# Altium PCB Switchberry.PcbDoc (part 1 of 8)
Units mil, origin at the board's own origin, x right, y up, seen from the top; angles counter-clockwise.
Board outline 4500 x 3824.8 mil, 6 copper layers (L01-TOP, L02-GND, L03-SIG, L04-SIG, L05-GND, L06-BOT), stack 49.214 mil thick; 431 components, 322 nets, 1699 pads, 1274 vias.
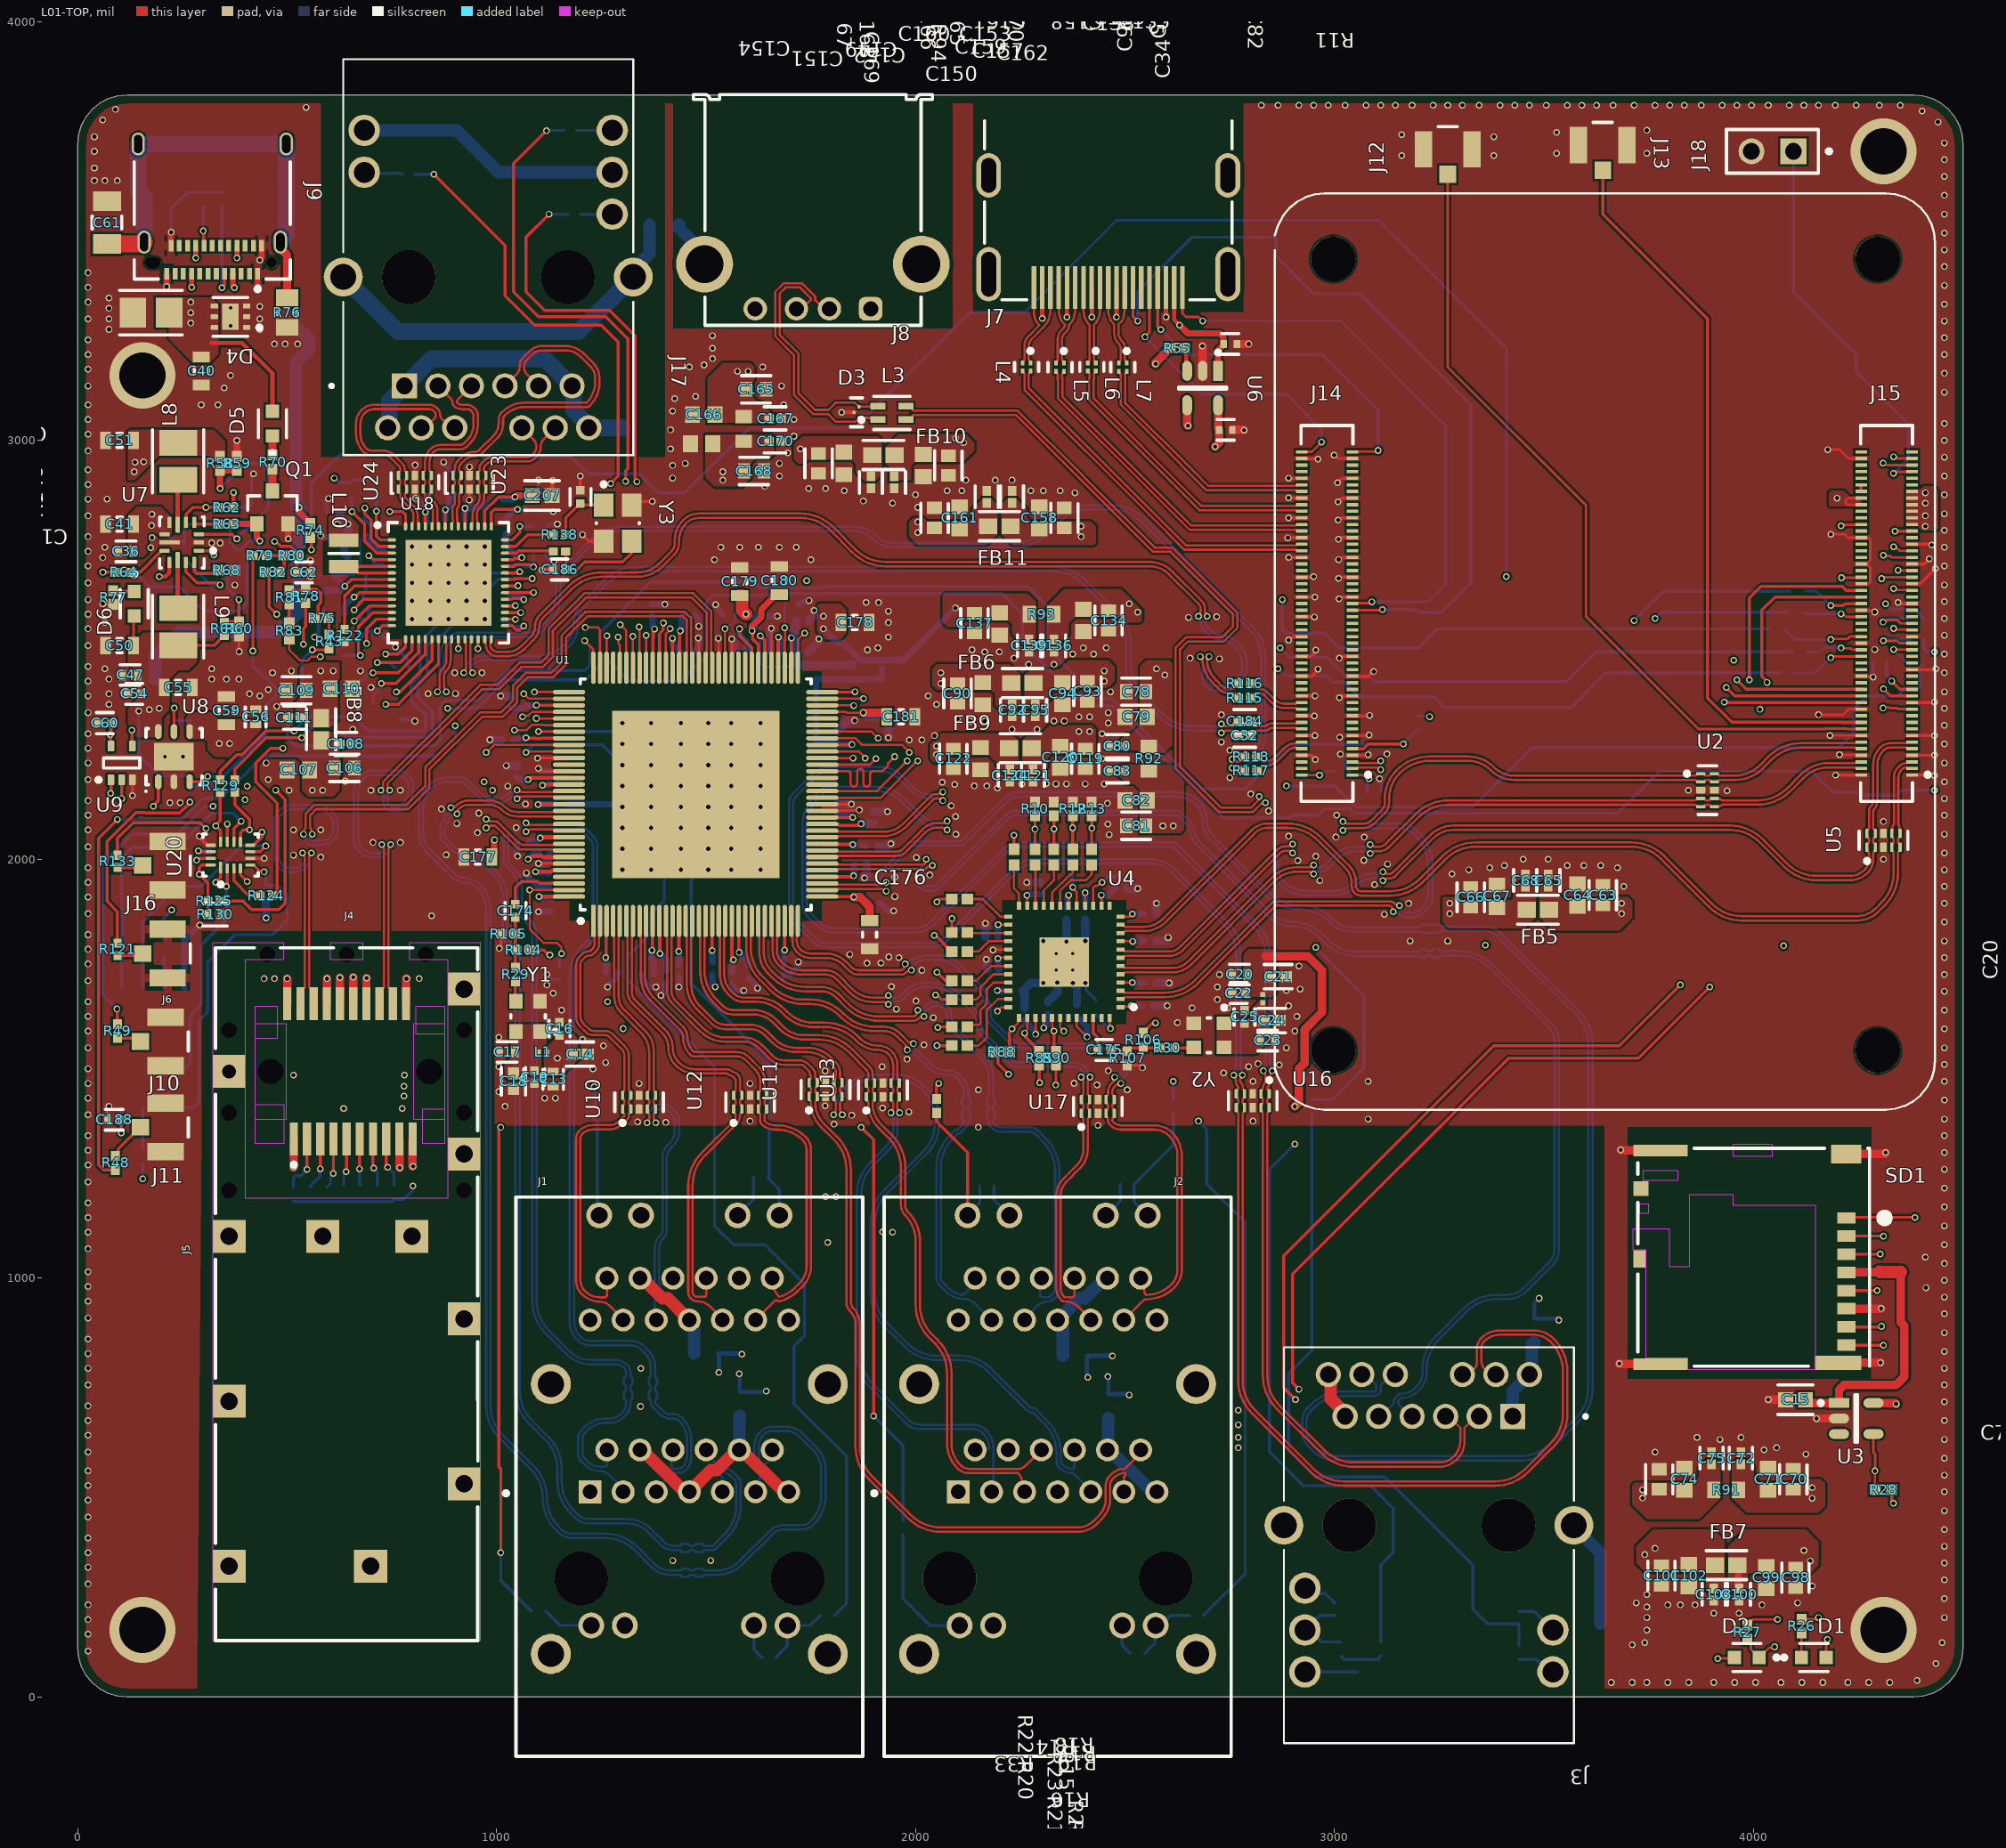
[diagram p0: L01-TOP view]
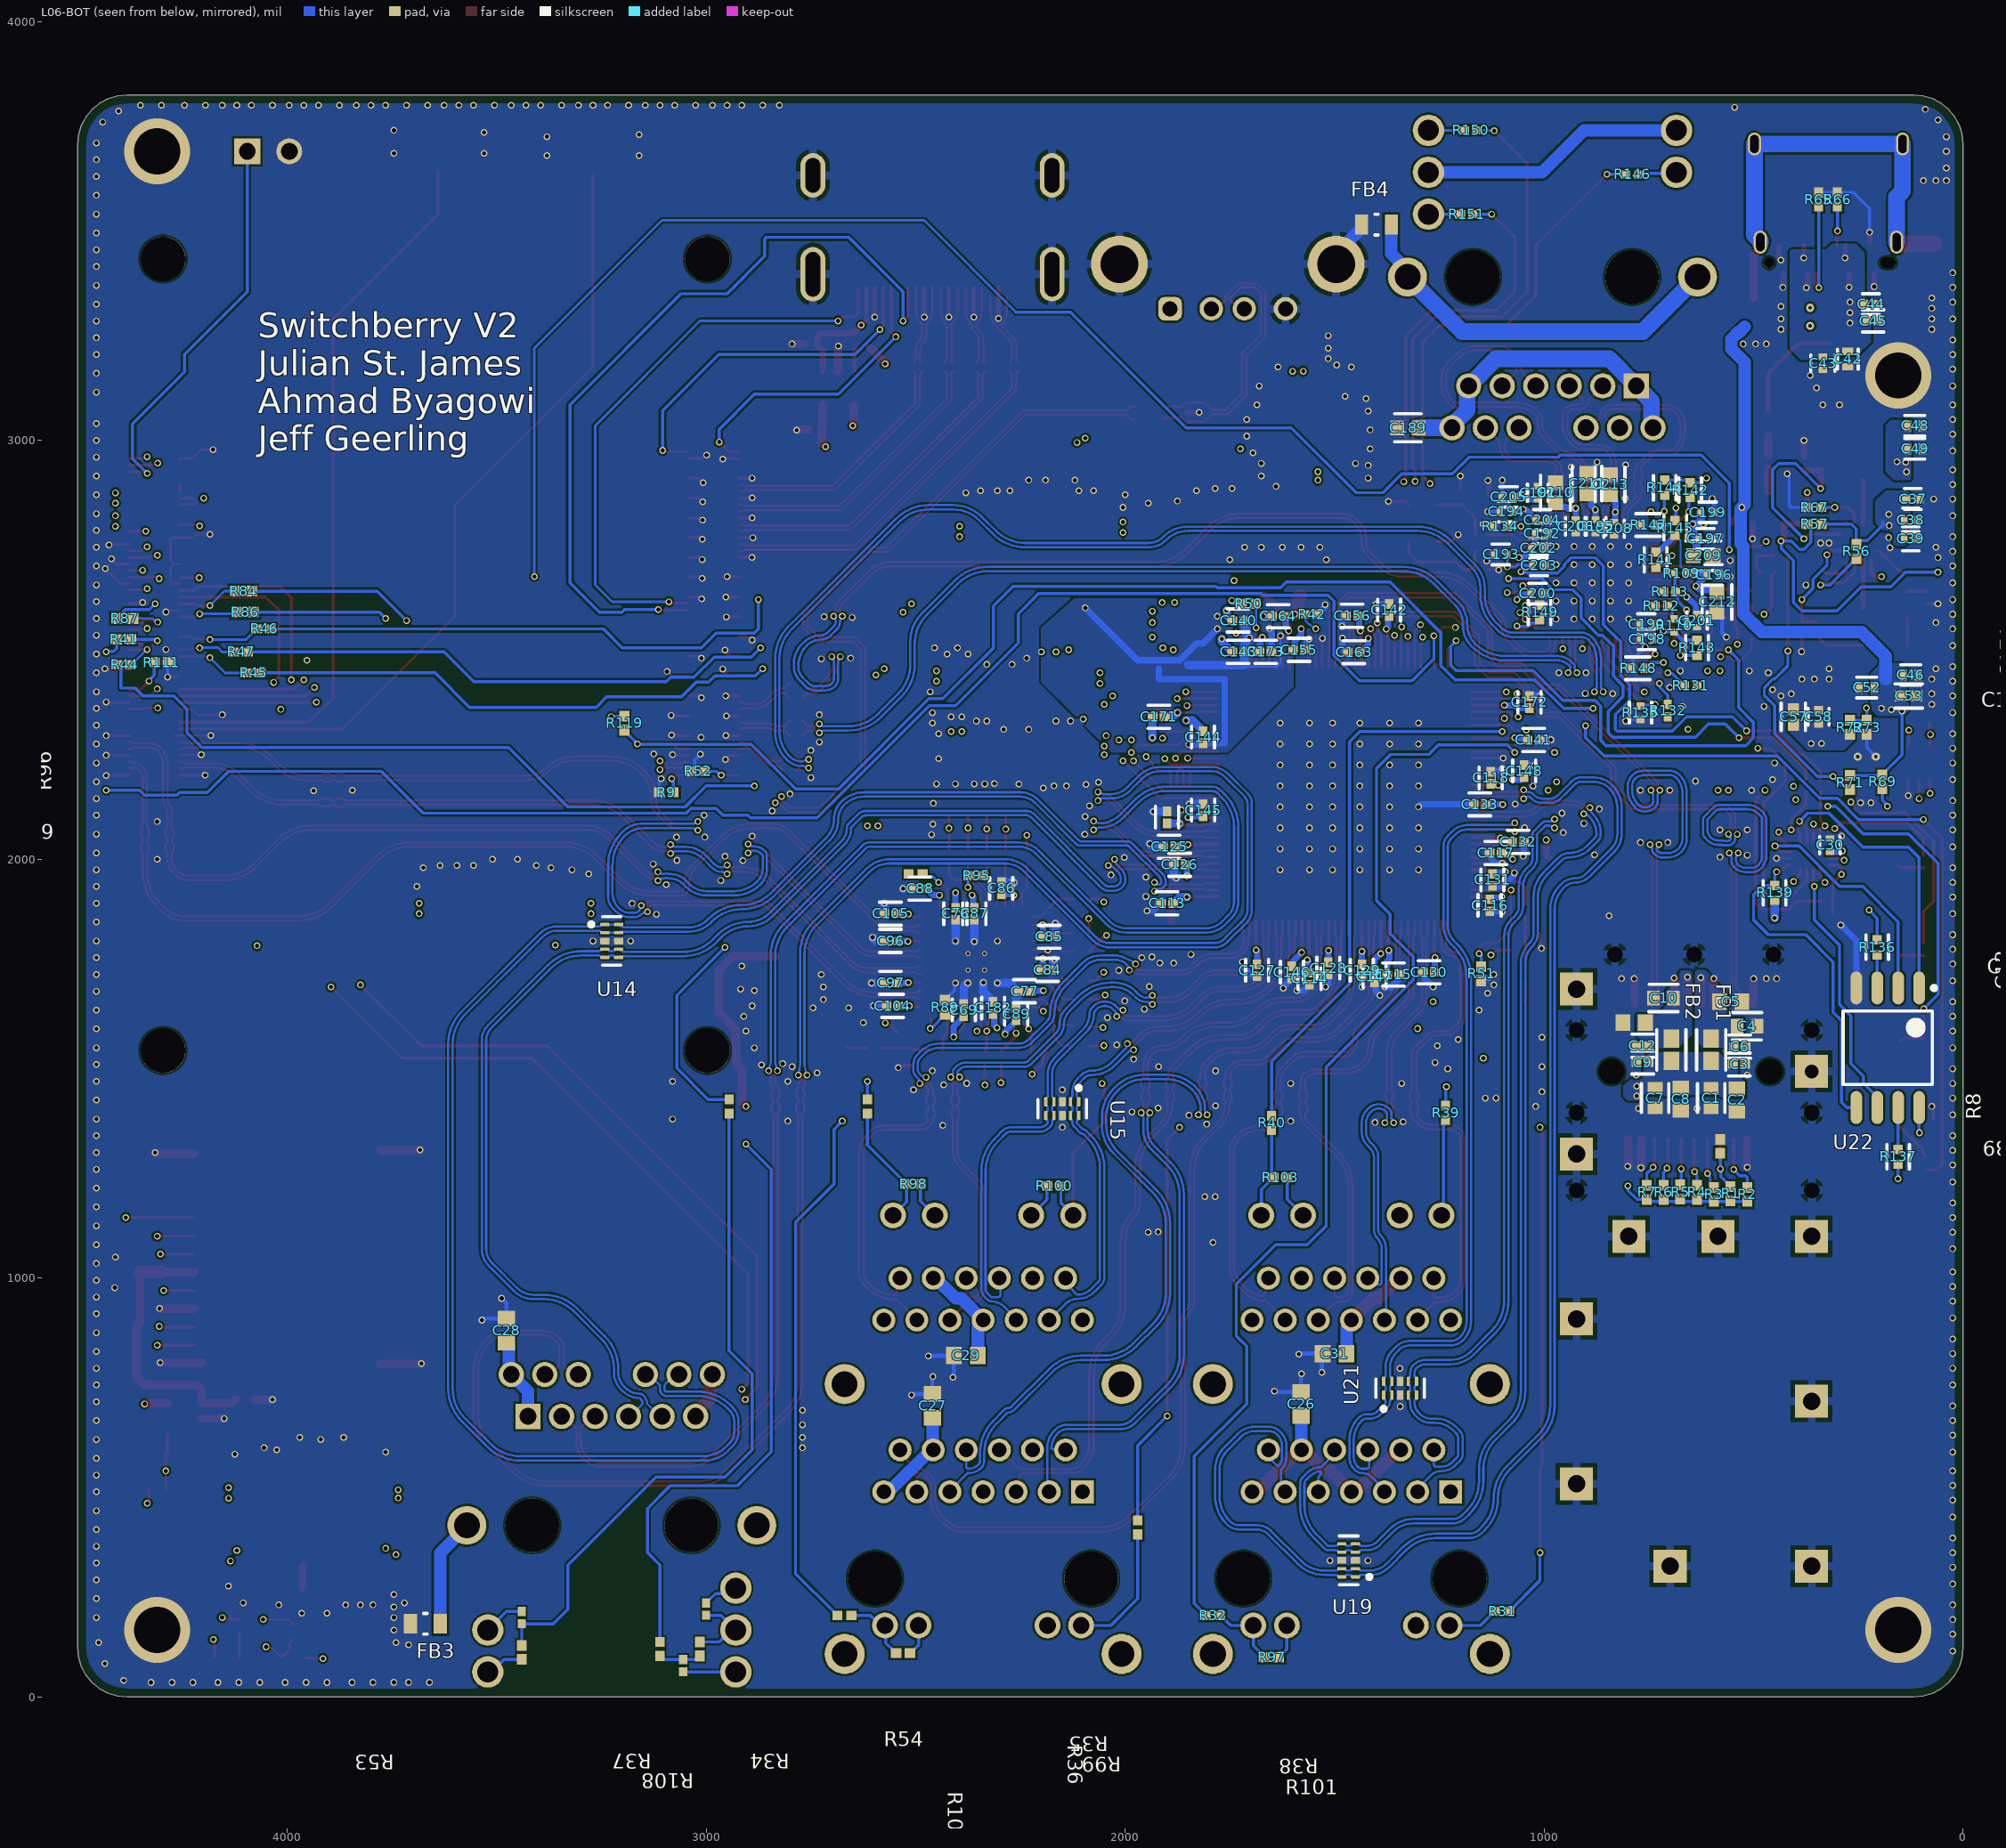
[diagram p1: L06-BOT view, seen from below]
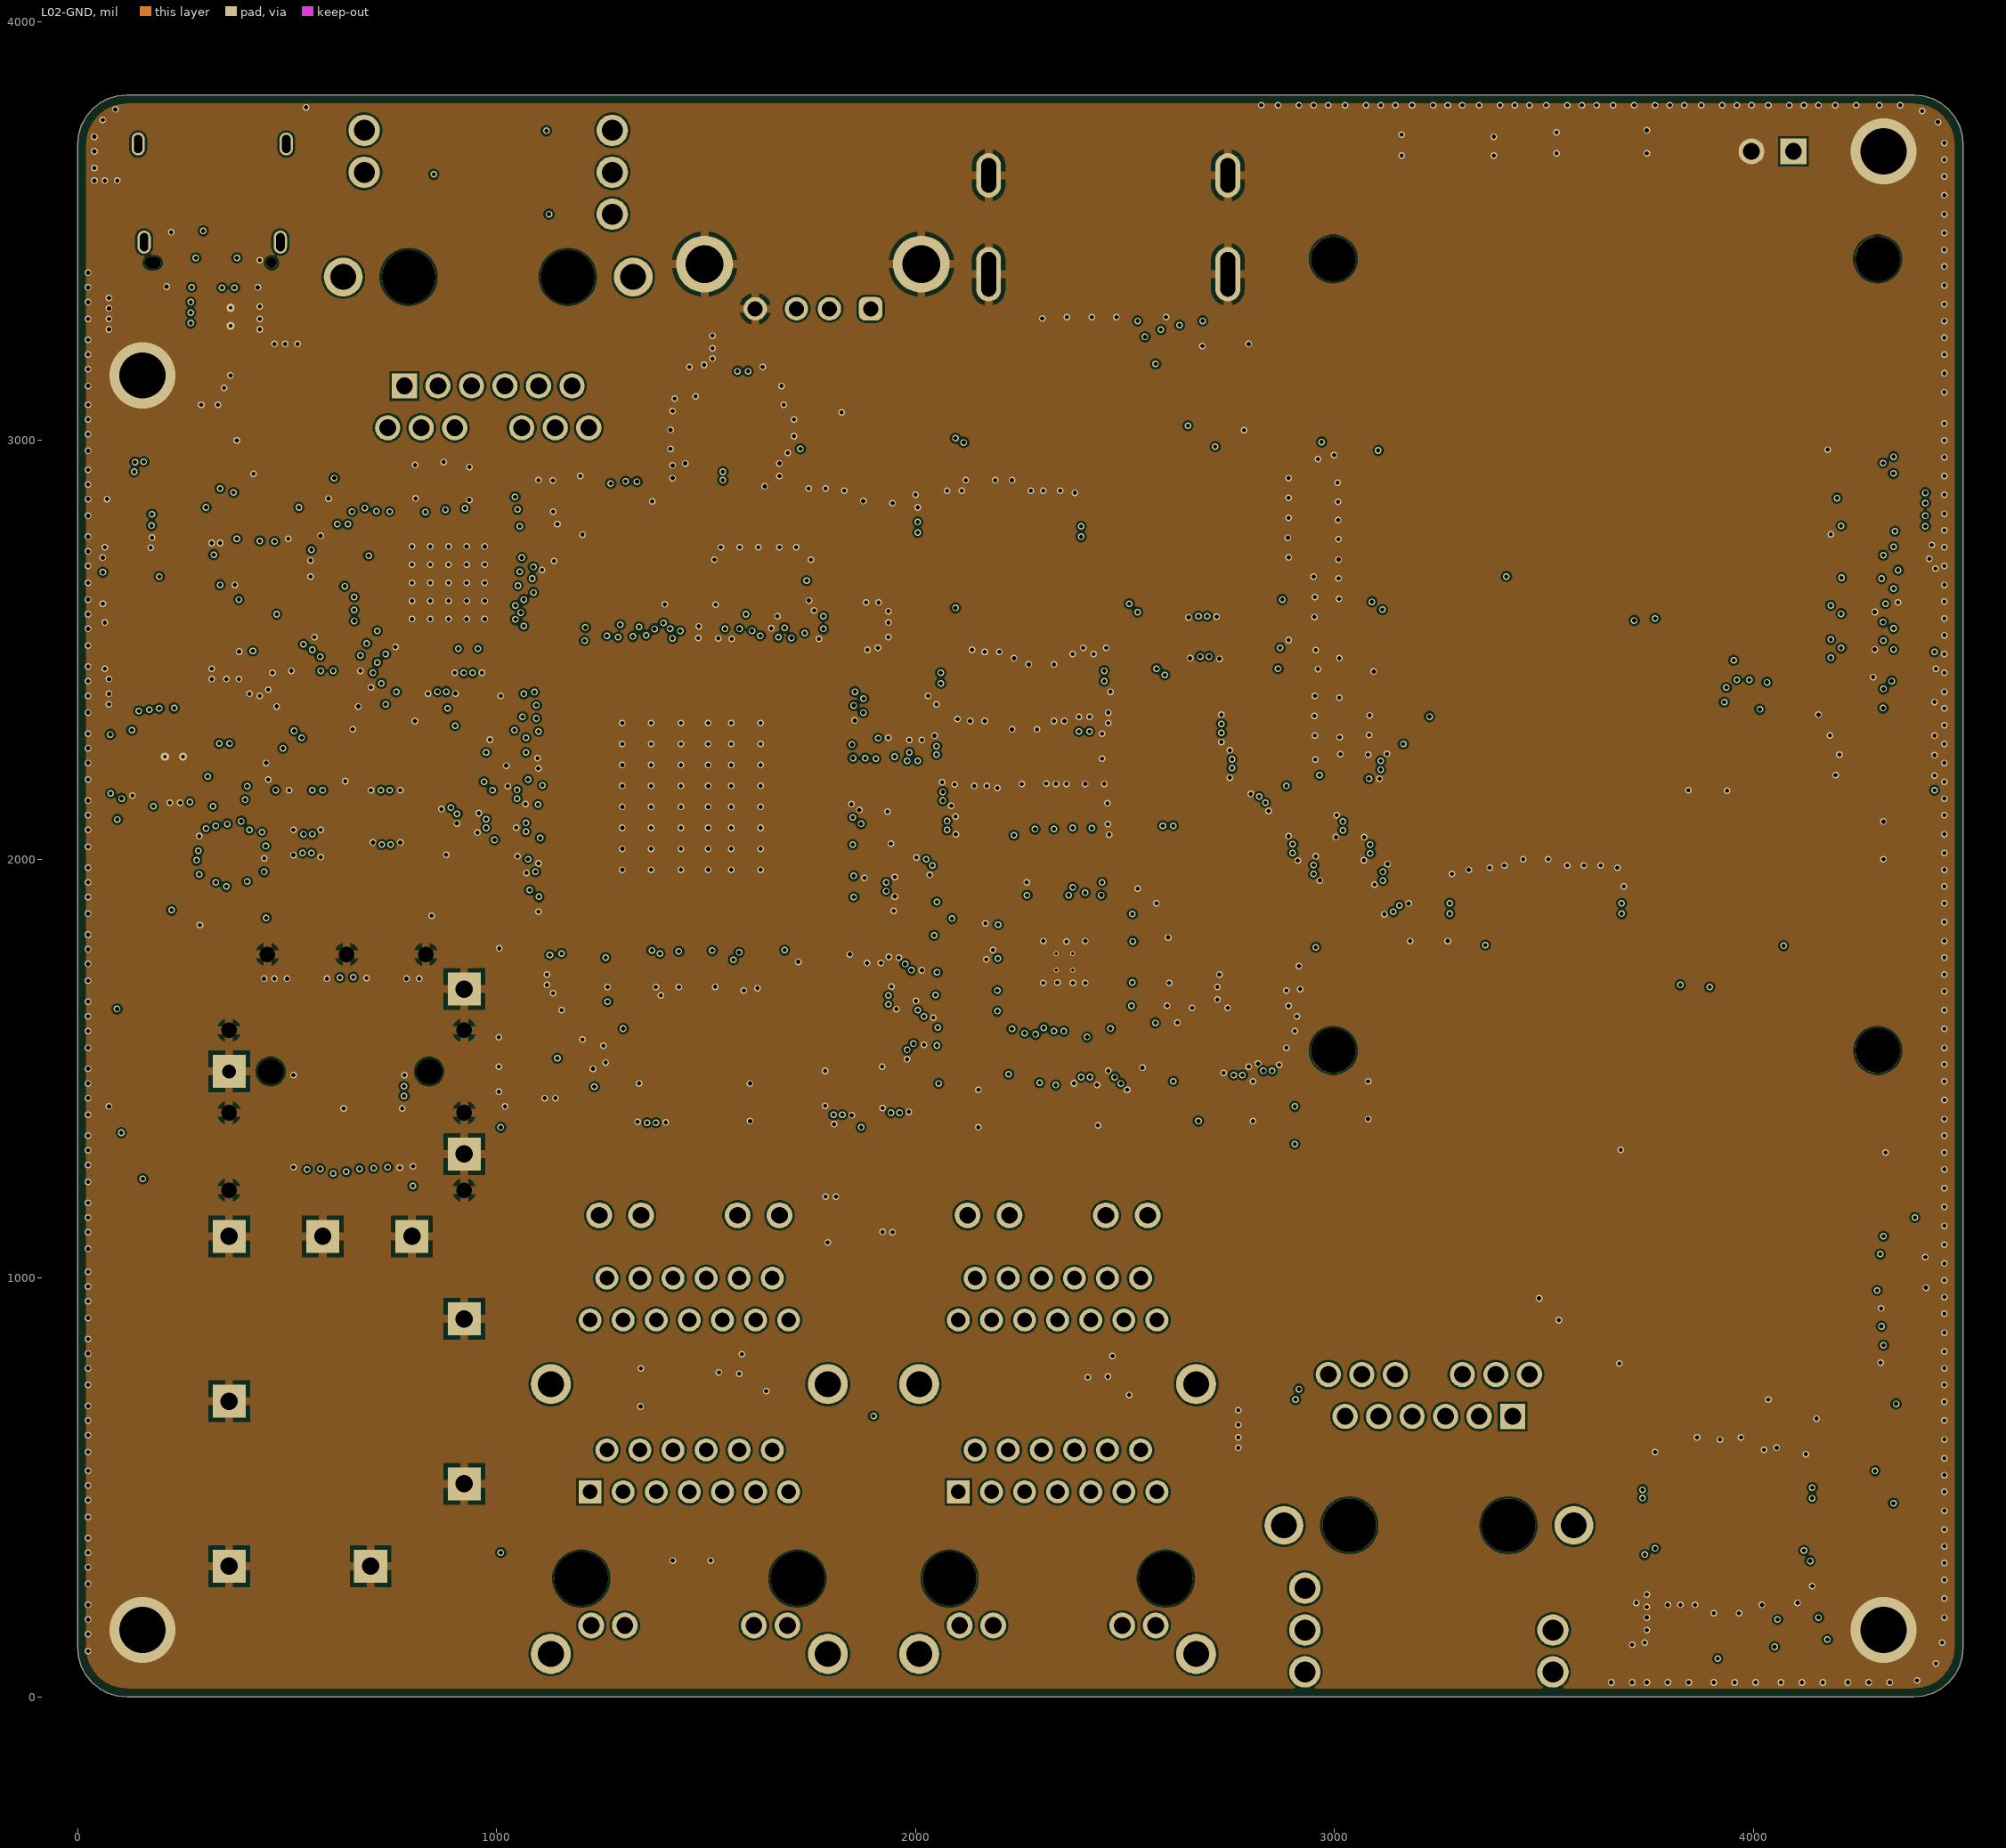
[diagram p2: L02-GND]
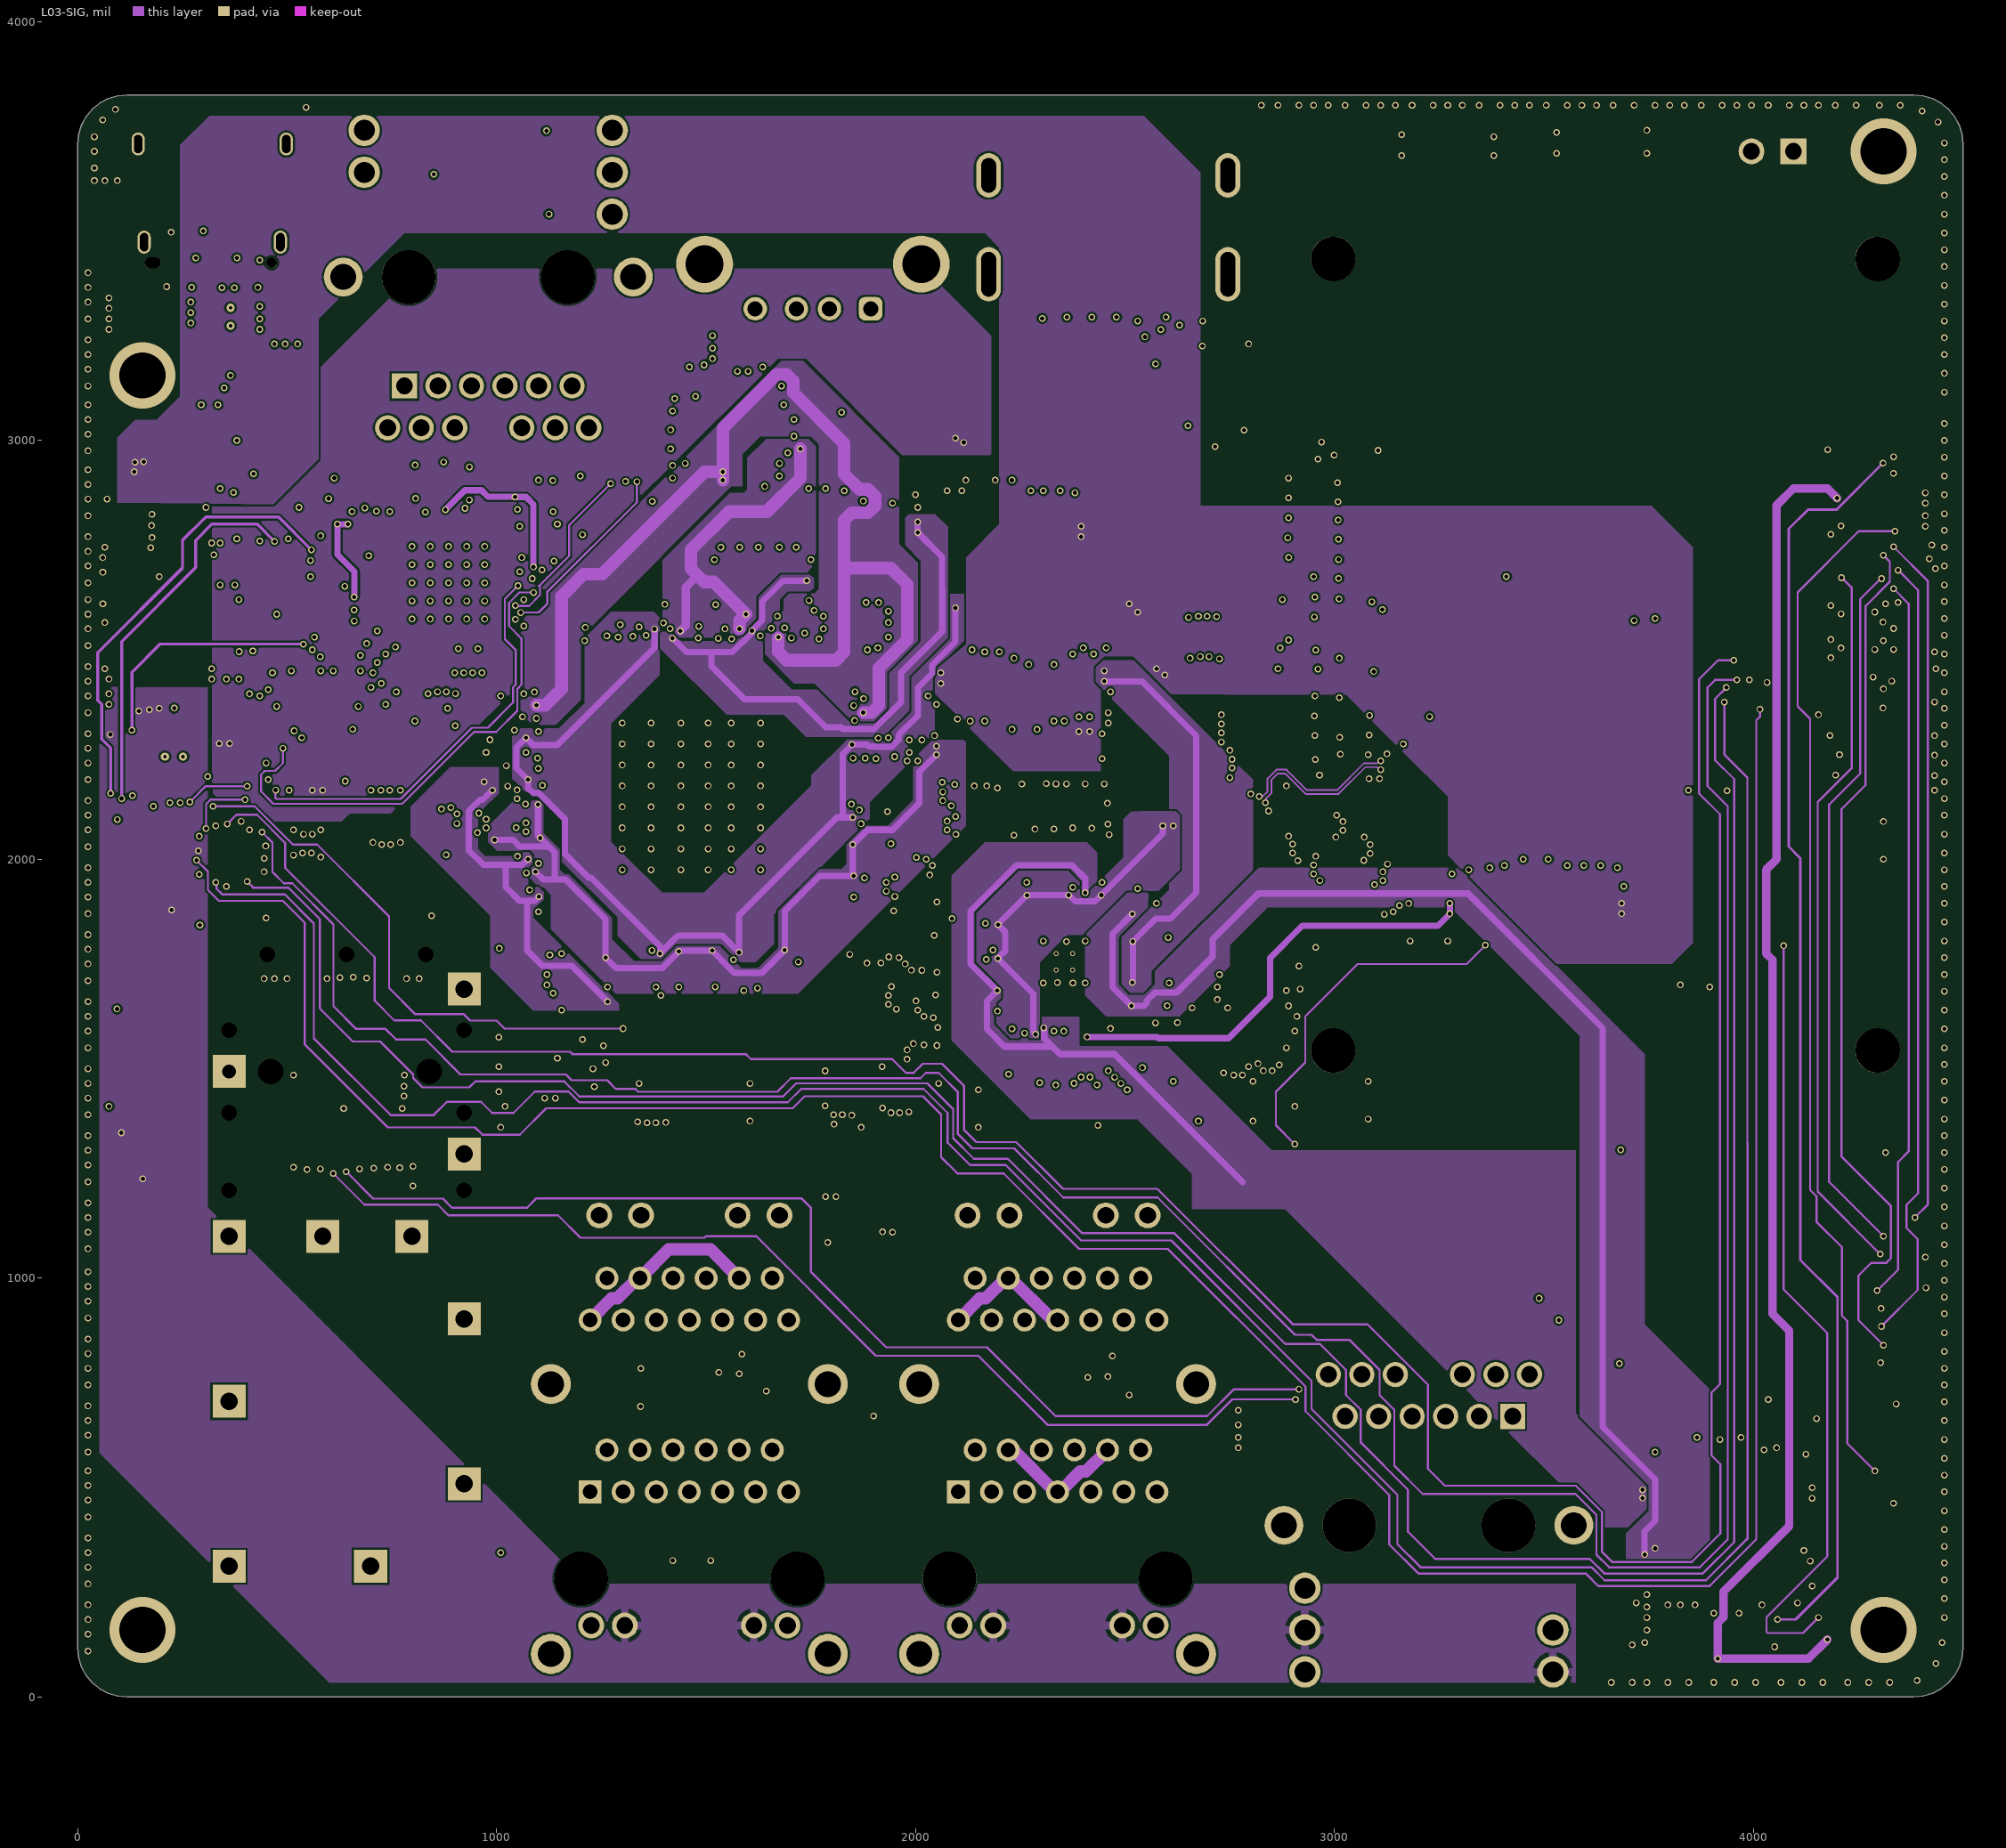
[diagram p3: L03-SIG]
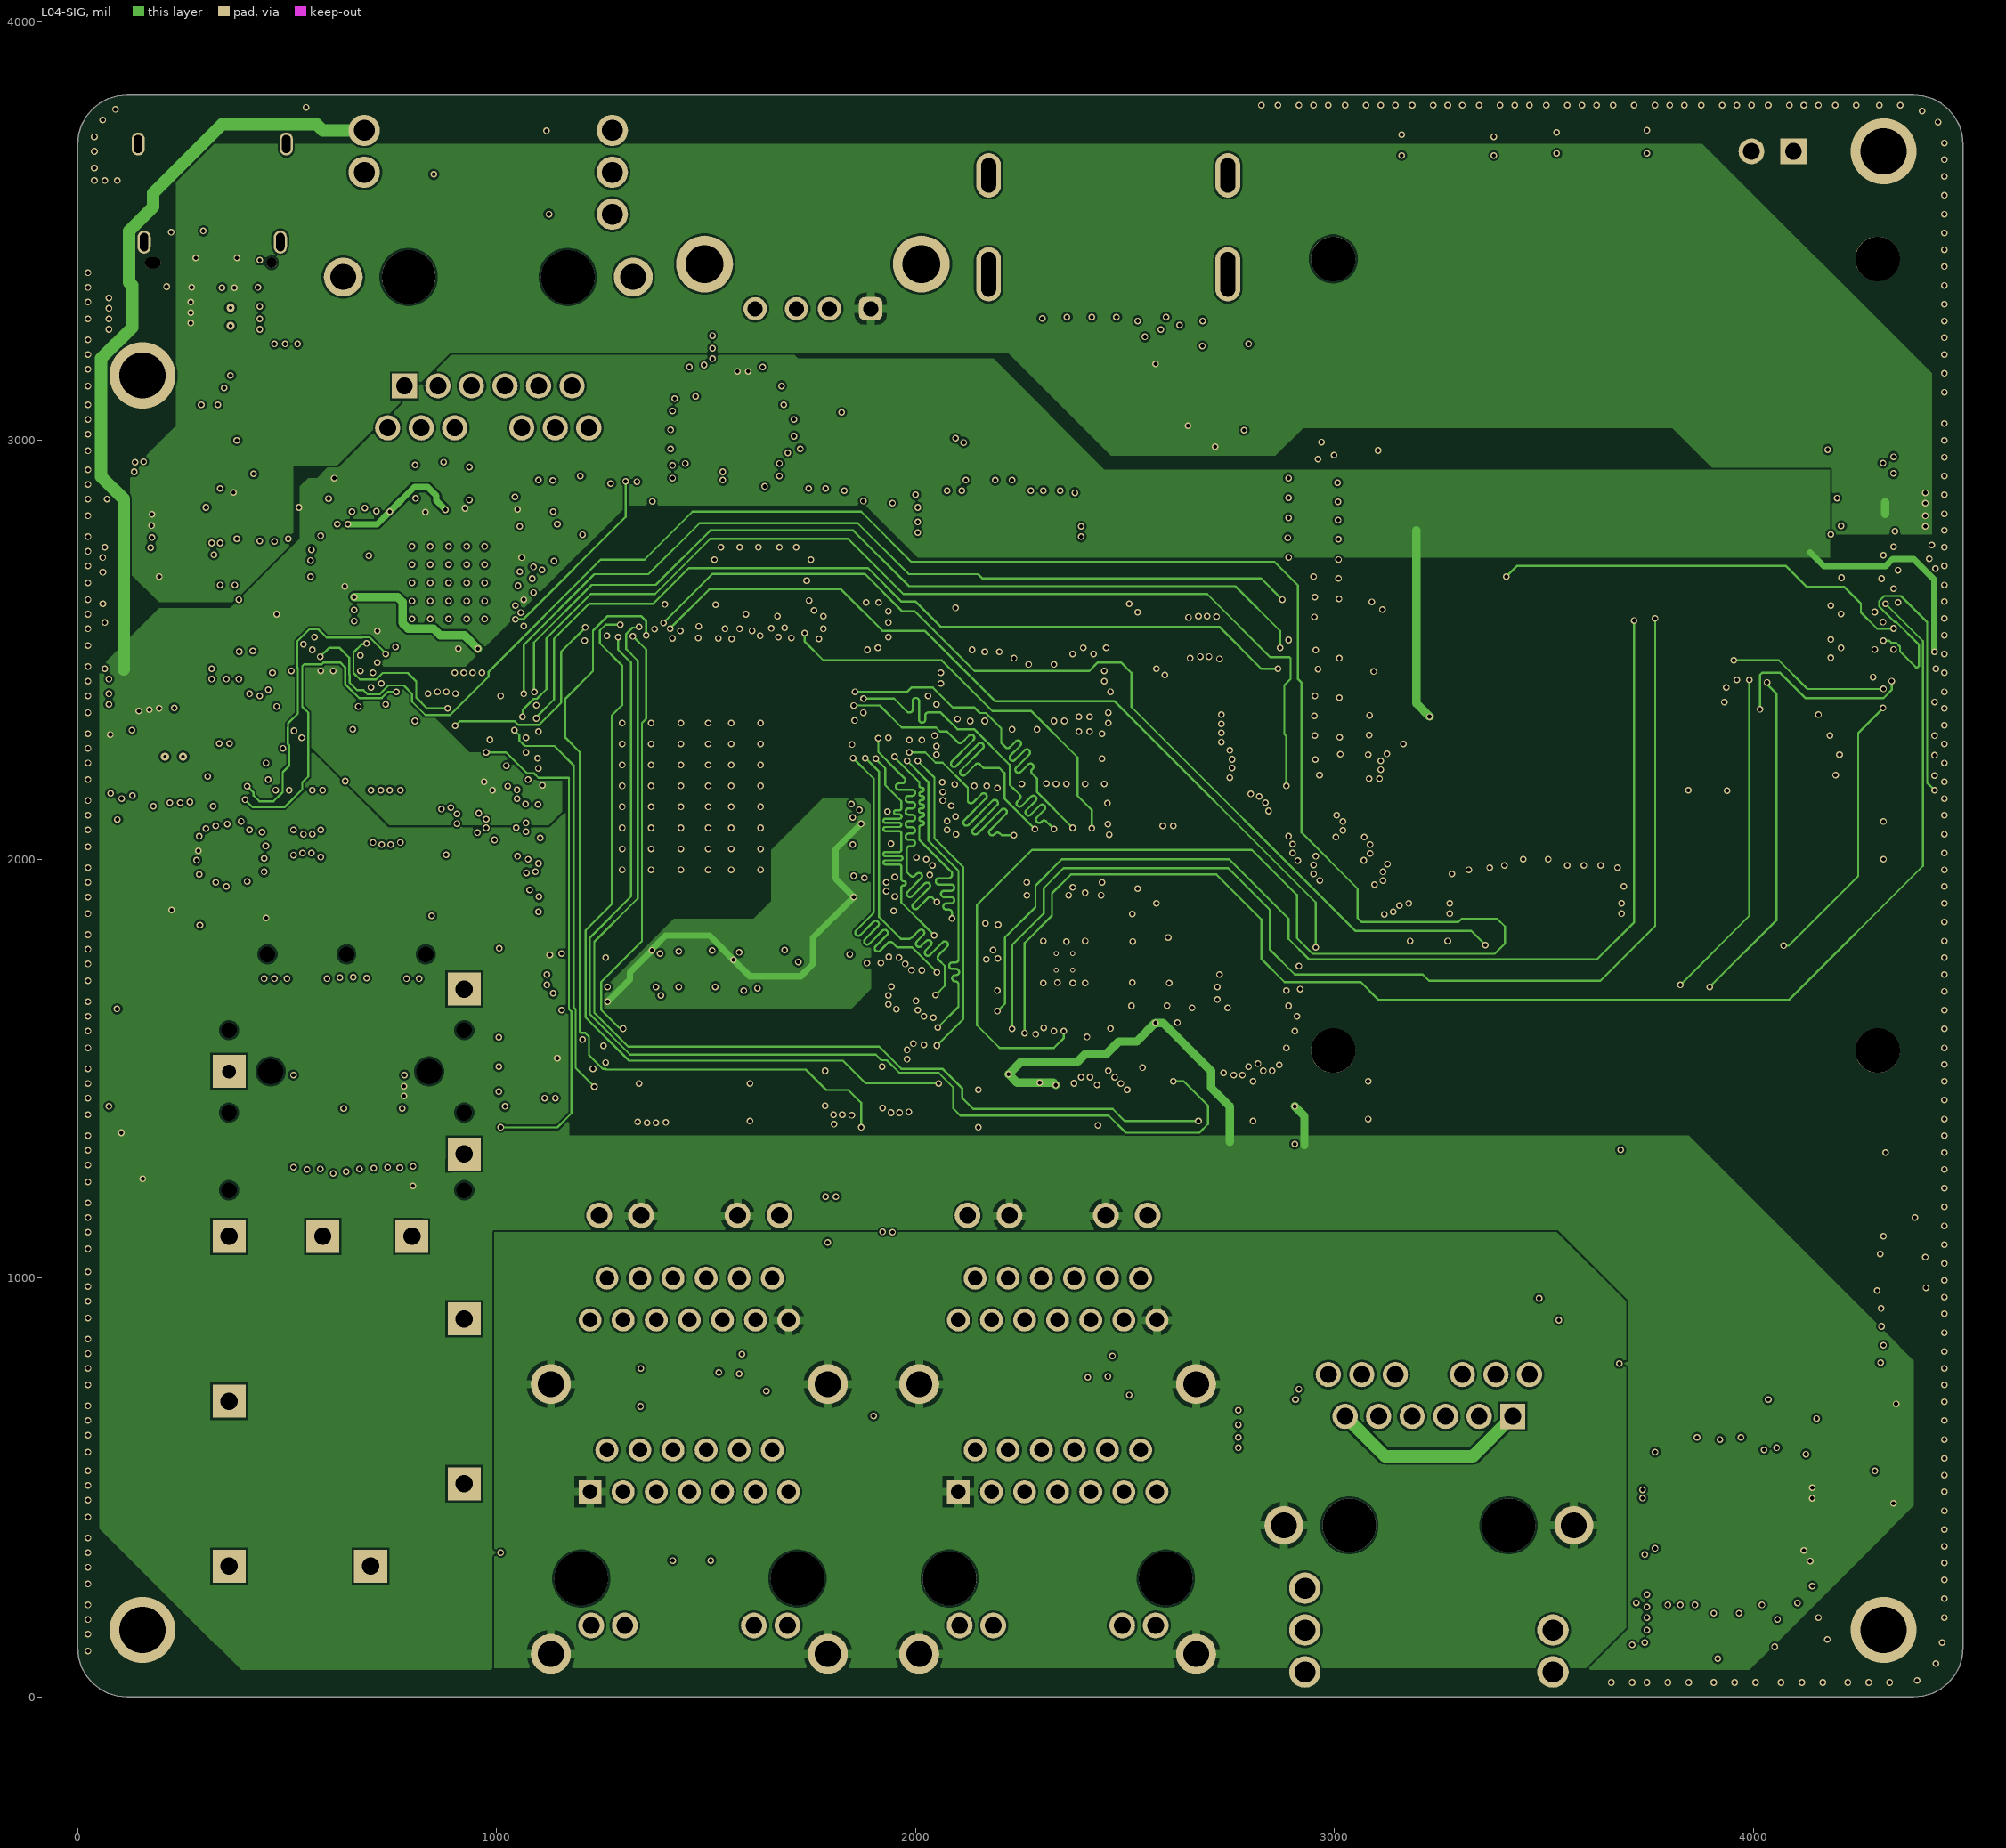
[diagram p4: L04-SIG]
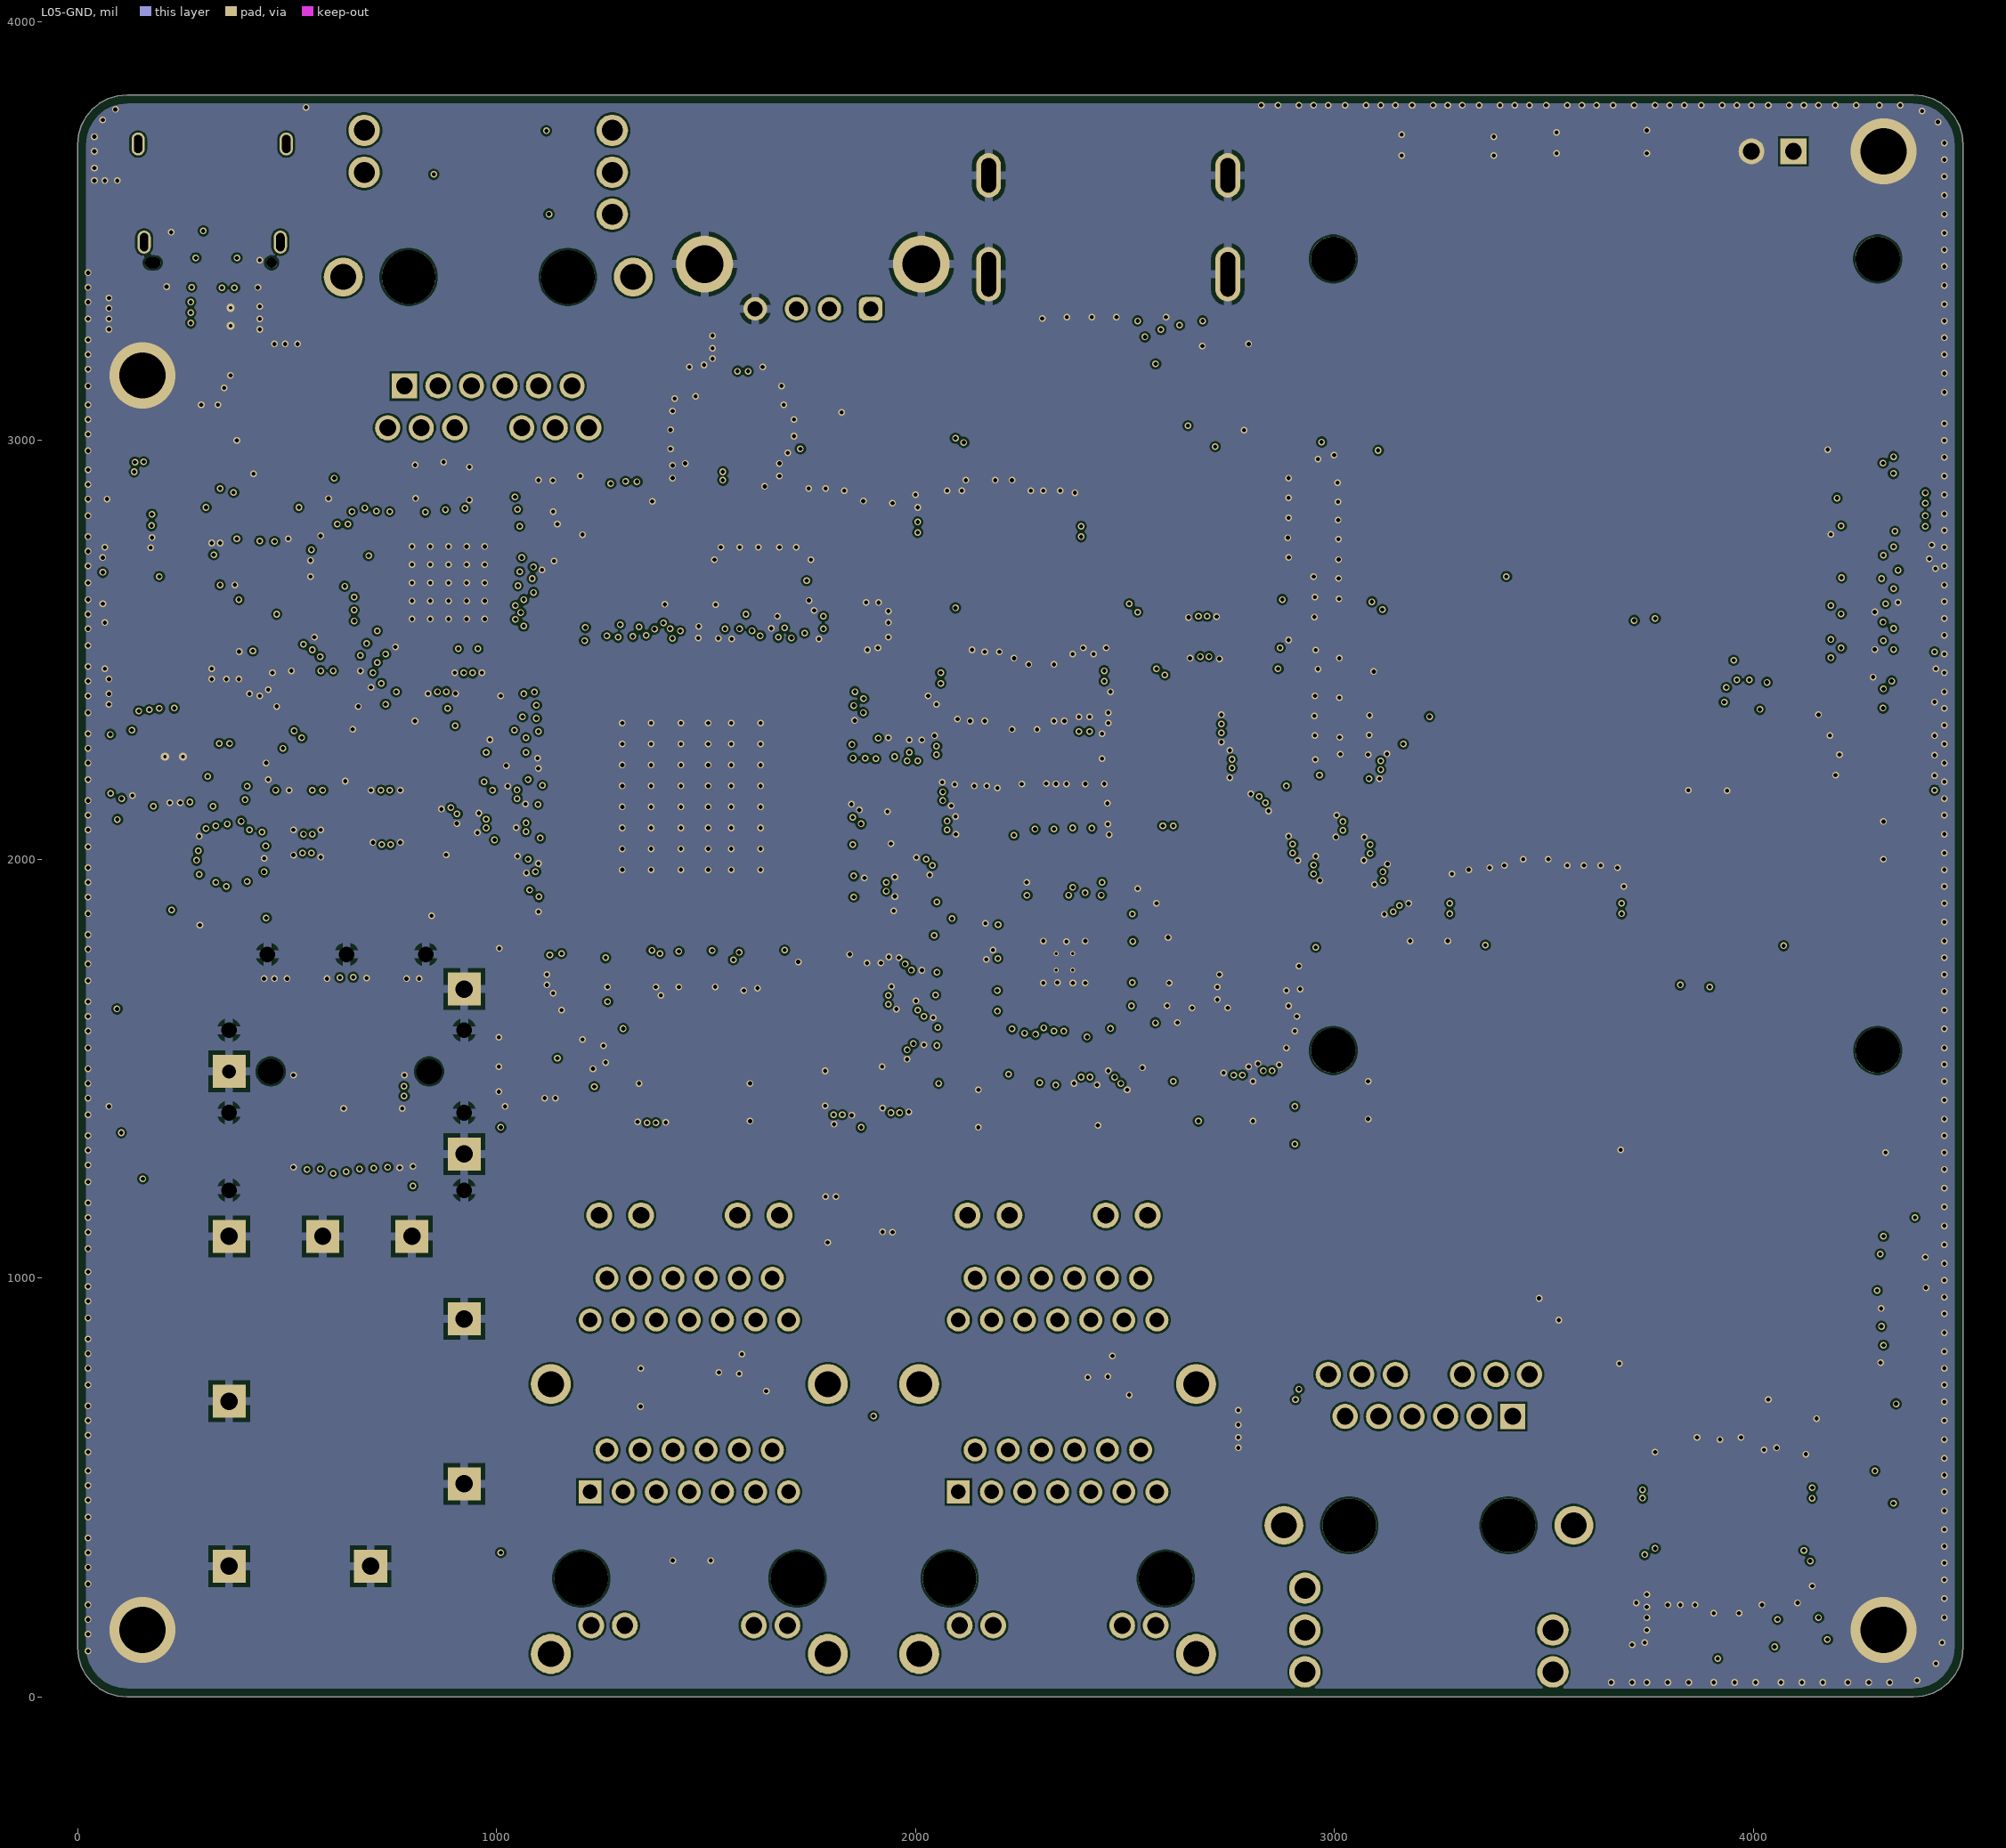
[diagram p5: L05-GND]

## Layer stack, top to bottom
Top Solder: solder mask 1, SM-001, Dk 4
L01-TOP: signal copper 1.378
Dielectric 1: prepreg 4.331, PP-017, Dk 4.3
L02-GND: signal copper 1.378
Dielectric 2: prepreg 4.331, PP-006, Dk 4.1
L03-SIG: signal copper 1.378
Dielectric 3: core 23.622, Core-039, Dk 4.8
L04-SIG: signal copper 1.378
Dielectric 4: prepreg 4.331, PP-006, Dk 4.1
L05-GND: signal copper 1.378
Dielectric 5: prepreg 4.331, PP-017, Dk 4.3
L06-BOT: signal copper 1.378
Bottom Solder: solder mask 1, SM-001, Dk 4

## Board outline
19.9,52.49 8.99,72.91 2.27,95.07 0,118.11 0,3706.69 2.27,3729.73 8.99,3751.89 19.9,3772.31 34.59,3790.21 52.49,3804.9 72.91,3815.81 95.07,3822.53 118.11,3824.8 4381.89,3824.8 4404.93,3822.53 4427.09,3815.81 4447.51,3804.9 4465.41,3790.21 4480.09,3772.31 4491.01,3751.89 4497.73,3729.73 4500,3706.69 4500,118.11 4497.73,95.07 4491.01,72.91 4480.09,52.49 4465.41,34.59 4447.51,19.9 4427.09,8.99 4404.93,2.27 4381.89,0 118.11,0 95.07,2.27 72.91,8.99 52.49,19.9 34.59,34.59

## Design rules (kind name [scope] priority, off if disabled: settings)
BoardOutlineClearance BoardOutlineClearance_Polygon [IsPolygon] p1: gap=20 ignorepadtopadclearanceinfootprint=FALSE
Clearance [All] p1: gap=5 ignorepadtopadclearanceinfootprint=FALSE
DiffPairsRouting [InDifferentialPairClass('All Differential Pairs')] p1: maxlimit=10 minlimit=5 mostfreqgap=5 toplayer_maxgap=5 toplayer_minwidth=5.38 toplayer_maxwidth=5.38 toplayer_prefwidth=5.38 midlayer1_maxgap=5 midlayer1_minwidth=4.04 midlayer1_maxwidth=4.04 midlayer1_prefwidth=4.04 midlayer2_maxgap=5 midlayer2_minwidth=4.04 midlayer2_maxwidth=4.04 midlayer2_prefwidth=4.04 bottomlayer_maxgap=5 bottomlayer_minwidth=5.38 bottomlayer_maxwidth=5.38 bottomlayer_prefwidth=5.38 impedanceprofiledriven=TRUE impedanceprofileid={2709FB12-8ABA-42C7-AB7C-5644AE441E76} impedanceprofilevalue=100.000000 maxuncoupledlength=500
HoleSize [All] p1: absolutevalues=TRUE maxlimit=120 minlimit=6 maxpercent=80.000 minpercent=20.000
PlaneClearance [All] p1: clearance=8
PlaneConnect [All] p1: planeconnectstyle=Direct reliefexpansion=20 reliefentries=4 reliefconductorwidth=10 reliefairgap=10
PolygonConnect ConnectorThermalRelief_Connect [All vs InComponent('J1') OR InComponent('J5') OR InComponent('J4') OR InComponent('J2') OR InComponent('J3') OR InComponent('SD1') OR InComponent('CM4') OR InComponent('J7') OR InComponent('J8') OR InComponent('J6') OR InComponent('J9')] p1: connectstyle=Relief reliefconductorwidth=20 reliefentries=4 polygonreliefangle="90 Angle" airgapwidth=10
PolygonConnect [All] p2: connectstyle=Direct reliefconductorwidth=10 reliefentries=4 polygonreliefangle="90 Angle" airgapwidth=10
RoutingVias [All] p1: holewidth=10 width=16 viastyle="Through Hole" minholewidth=6 minwidth=10 maxholewidth=50 maxwidth=100
SolderMaskExpansion [All] p1: expansion=4 istentingtop=FALSE
SupplyNets "Schematic Supply Nets_4" [InNet('P0V95_I225')] p1: voltage=0.000
SupplyNets "Schematic Supply Nets_24" [InNet('SW_AVDDL')] p2: voltage=0.000
SupplyNets "Schematic Supply Nets_23" [InNet('SW_VDDHS')] p3: voltage=0.000
SupplyNets "Schematic Supply Nets_22" [InNet('SW_DVDDL')] p4: voltage=0.000
SupplyNets "Schematic Supply Nets_21" [InNet('SW_VDDIO')] p5: voltage=0.000
SupplyNets "Schematic Supply Nets_20" [InNet('CHASSIS_GND')] p6: voltage=0.000
SupplyNets "Schematic Supply Nets_19" [InNet('SW_AVDDH')] p7: voltage=0.000
SupplyNets "Schematic Supply Nets_18" [InNet('CHASSIS_CM4_GND')] p8: voltage=0.000
SupplyNets "Schematic Supply Nets_17" [InNet('P2V5')] p9: voltage=0.000
SupplyNets "Schematic Supply Nets_16" [InNet('SW_VDDLS')] p10: voltage=0.000
SupplyNets "Schematic Supply Nets_15" [InNet('PHY_AVDDL')] p11: voltage=0.000
SupplyNets "Schematic Supply Nets_14" [InNet('P1V2')] p12: voltage=0.000
SupplyNets "Schematic Supply Nets_13" [InNet('PHY_AVDDL_PLL')] p13: voltage=0.000
SupplyNets "Schematic Supply Nets_12" [InNet('PHY_AVDDH')] p14: voltage=0.000
SupplyNets "Schematic Supply Nets_11" [InNet('PHY_DVDDL')] p15: voltage=0.000
SupplyNets "Schematic Supply Nets_10" [InNet('PHY_DVDDH')] p16: voltage=0.000
SupplyNets "Schematic Supply Nets_9" [InNet('P3V3_CM4')] p17: voltage=0.000
SupplyNets "Schematic Supply Nets_8" [InNet('P5V')] p18: voltage=0.000
SupplyNets "Schematic Supply Nets_7" [InNet('5V_HDMI')] p19: voltage=0.000
SupplyNets "Schematic Supply Nets_6" [InNet('SFP1_VCCT')] p20: voltage=0.000
SupplyNets "Schematic Supply Nets_5" [InNet('GND')] p21: voltage=0.000
SupplyNets "Schematic Supply Nets_2" [InNet('SFP1_VCCR')] p22: voltage=0.000
SupplyNets "Schematic Supply Nets_1" [InNet('1V8')] p23: voltage=0.000
SupplyNets "Schematic Supply Nets" [InNet('P3V3')] p24: voltage=0.000
Width [All] p1: maxlimit=150 minlimit=4.5 preferedwidth=10 toplayer_maxwidth=100 toplayer_prefwidth=7.27 midlayer1_maxwidth=100 midlayer1_prefwidth=4.97 midlayer2_maxwidth=100 midlayer2_prefwidth=4.97 bottomlayer_maxwidth=100 bottomlayer_prefwidth=7.27 minimp=50.000000 maximp=50.000000 favimp=50.000000
26 further rules are at their usual default settings.

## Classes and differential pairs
component class 21-I225_2: C189 C190 C191 C192 C193 C194 C195 C196 C197 C198 C199 C200 C201 C202 C203 C204 C205 C206 C207 C208 C209 C210 C211 C212 C213 FB4 J J17 R141 R142 R143 R144 R145 R146 R147 R148 R149 R150 R151 U23 U24
component class 20-I225_1: C30 C32 C184 C186 C187 C188 J6 J16 L10 R109 R110 R111 R112 R113 R115 R116 R117 R118 R119 R121 R122 R124 R125 R126 R129 R130 R131 R132 R133 R134 R135 R136 R137 R138 R139 R140 U18 U20 U22 X1 Y3
component class 11-Switch_Strapping: R97 R98 R99 R100 R101 R102 R103
differential pair class HDMI: CON_HDMI0_CLK CON_HDMI0_TX0 CON_HDMI0_TX1 CON_HDMI0_TX2
component class 09-Switch_Power_Filters: C106 C107 C108 C109 C110 C111 C112 C113 C114 C115 C116 C117 C118 C119 C120 C121 C122 C123 C124 C125 C126 C127 C128 C129 C130 C131 C132 C133 C134 C135 C136 C137 C138 C139 C140 C141 C142 C143 C144 C145 C146 C147 C148 C149 C150 C151 C152 C153 C154 C155 C156 C157 C158 C159 C160 C161 C162 C163 C164 C165 C166 C167 C168 C169 C170 C171 C172 C173 C176 C177 C178 C179 C180 C181 FB8 FB9 FB10 FB11 R93 R94
component class 08-Power: C35 C36 C37 C38 C39 C40 C41 C42 C43 C44 C45 C46 C47 C48 C49 C50 C51 C52 C53 C54 C55 C56 C57 C58 C59 C60 C61 C62 D4 D5 D6 J9 L8 L9 Q1 R56 R57 R58 R59 R60 R61 R62 R63 R64 R65 R66 R67 R68 R69 R70 R71 R72 R73 R74 R75 R76 R77 R78 R79 R80 R81 R82 U7 U8 U9
component class 10-RJ45_Protection: U10 U11 U12 U13 U14 U15 U16 U17 U19 U21
component class 02-Clocks: C13 C14 C16 C17 C18 C19 C20 C21 C22 C23 C24 C25 C174 C175 L1 L2 R29 R30 R104 R105 R106 R107 Y1 Y2
component class 07-KSZ9031_1G_BASET_XCVR: C63 C64 C65 C66 C67 C68 C69 C70 C71 C72 C73 C74 C75 C76 C77 C78 C79 C80 C81 C82 C83 C84 C85 C86 C87 C88 C89 C90 C91 C92 C93 C94 C95 C96 C97 C98 C99 C100 C101 C102 C103 C104 C105 C182 FB5 FB6 FB7 R14 R15 R16 R17 R18 R19 R20 R21 R22 R23 R24 R25 R83 R84 R85 R86 R87 R88 R89 R90 R91 R92 R95 R96 U2 U4 U5
component class 06-CM4_USB_HDMI_SDCard: C15 C33 C34 D3 J7 J8 L3 L4 L5 L6 L7 R28 R55 SD1 U3 U6
component class 03-KSZ9567: J10 J11 R10 R11 R12 R13 R31 R32 R33 R34 R35 R36 R37 R38 R39 R40 R41 R42 R43 R44 R45 R46 R47 R48 R49 R50 R51 U1
net class 01-CM4_Conn_Nets: 1V8 BRD_RST_N CM4_GPIO13 CM4_GPIO19 CM4_GPIO20 CM4_GPIO21 CM4_GPIO26 CM_GPIOx ETH_LED1 ETH_LED2 ETH_LED3 ETH_PAIR0_N ETH_PAIR0_P ETH_PAIR1_N ETH_PAIR1_P ETH_PAIR2_N ETH_PAIR2_P ETH_PAIR3_N ETH_PAIR3_P ETH_SYNC_IN ETH_SYNC_OUT GND GPIO_VREF HDMI0_CEC HDMI0_CLK_N HDMI0_CLK_P HDMI0_HP HDMI0_SCL HDMI0_SDA HDMI0_TX0_N HDMI0_TX0_P HDMI0_TX1_N HDMI0_TX1_P HDMI0_TX2_N HDMI0_TX2_P LED_ACT LED_PWR NetCM1_20 NetCM1_49 NetCM1_76 NetCM1_104 NetCM1_106 NetCM1_119 NetD1_1 NetD2_1 NetJ15_51 NetJ15_55 nRPIBOOT P3V3_CM4 P5V PCIe_CLK_N PCIe_CLK_P PCIE_CLK_REQ_N PCIE_PERST_N PCIe_RX_N PCIe_RX_P PCIe_TX_N PCIe_TX_P PHY_INT_N PHY_MDC PHY_MDIO SD_CLK SD_CMD SD_DAT0 SD_DAT1 SD_DAT2 SD_DAT3 SD_PWR_ON SFP1_SCL SFP1_SDA SPI0_CE0 SPI0_CLK SPI0_MISO SPI0_MOSI SW_INTR_N USB_N USB_OTG USB_P
component class 04-Switch_RJ45: C26 C27 C28 C29 C31 FB3 J1 J2 J3 R53 R54 R108
component class 05-Switch_SFP_CM4_RJ45: C1 C2 C3 C4 C5 C6 C7 C8 C9 C10 C11 C12 FB1 FB2 J4 J5 R1 R2 R3 R4 R5 R6 R7 R8
component class 01-CM4_Conn: D1 D2 J12 J13 J14 J15 J18 R9 R26 R27 R52
differential pair PCIE_TX: +PCIe_TX_P -PCIe_TX_N
differential pair PCIE_RX: +PCIe_RX_P -PCIe_RX_N
differential pair PCIE_CLK: +PCIe_CLK_P -PCIe_CLK_N
differential pair PCIE_CLK_R: +PCIE_CLK_R_P -PCIE_CLK_R_N
differential pair MDI_D: +MDI_D_P -MDI_D_N
differential pair MDI_C: +MDI_C_P -MDI_C_N
differential pair MDI_B: +MDI_B_P -MDI_B_N
differential pair MDI_A: +MDI_A_P -MDI_A_N
differential pair I225_PE_TX: +I225_PE_TX_P -I225_PE_TX_N
differential pair I225_PE_RX: +I225_PE_RX_P -I225_PE_RX_N
differential pair ETH_PAIR3: +ETH_PAIR3_P -ETH_PAIR3_N
differential pair ETH_PAIR2: +ETH_PAIR2_P -ETH_PAIR2_N
differential pair ETH_PAIR1: +ETH_PAIR1_P -ETH_PAIR1_N
differential pair ETH_PAIR0: +ETH_PAIR0_P -ETH_PAIR0_N
differential pair USB: +USB_P -USB_N
differential pair USB_FILT: +USB_FILT_P -USB_FILT_N
differential pair CON_HDMI0_TX2: +CON_HDMI0_TX2_P -CON_HDMI0_TX2_N
differential pair CON_HDMI0_TX1: +CON_HDMI0_TX1_P -CON_HDMI0_TX1_N
differential pair CON_HDMI0_TX0: +CON_HDMI0_TX0_P -CON_HDMI0_TX0_N
differential pair CON_HDMI0_CLK: +CON_HDMI0_CLK_P -CON_HDMI0_CLK_N
differential pair SW_SFP: +SW_SFP_P -SW_SFP_N
differential pair SFP_SW: +SFP_SW_P -SFP_SW_N
differential pair P5_TXRXD: +P5_TXRXD_P -P5_TXRXD_N
differential pair P5_TXRXC: +P5_TXRXC_P -P5_TXRXC_N
differential pair P5_TXRXB: +P5_TXRXB_P -P5_TXRXB_N
differential pair P5_TXRXA: +P5_TXRXA_P -P5_TXRXA_N
differential pair P4_TXRXD: +P4_TXRXD_P -P4_TXRXD_N
differential pair P4_TXRXC: +P4_TXRXC_P -P4_TXRXC_N
differential pair P4_TXRXB: +P4_TXRXB_P -P4_TXRXB_N
differential pair P4_TXRXA: +P4_TXRXA_P -P4_TXRXA_N
differential pair P3_TXRXD: +P3_TXRXD_P -P3_TXRXD_N
differential pair P3_TXRXC: +P3_TXRXC_P -P3_TXRXC_N
differential pair P3_TXRXB: +P3_TXRXB_P -P3_TXRXB_N
differential pair P3_TXRXA: +P3_TXRXA_P -P3_TXRXA_N
differential pair P2_TXRXD: +P2_TXRXD_P -P2_TXRXD_N
differential pair P2_TXRXC: +P2_TXRXC_P -P2_TXRXC_N
differential pair P2_TXRXB: +P2_TXRXB_P -P2_TXRXB_N
differential pair P2_TXRXA: +P2_TXRXA_P -P2_TXRXA_N
differential pair P1_TXRXD: +P1_TXRXD_P -P1_TXRXD_N
differential pair P1_TXRXC: +P1_TXRXC_P -P1_TXRXC_N
differential pair P1_TXRXB: +P1_TXRXB_P -P1_TXRXB_N
differential pair P1_TXRXA: +P1_TXRXA_P -P1_TXRXA_N
differential pair HDMI0_TX2: +HDMI0_TX2_P -HDMI0_TX2_N
differential pair HDMI0_TX1: +HDMI0_TX1_P -HDMI0_TX1_N
differential pair HDMI0_TX0: +HDMI0_TX0_P -HDMI0_TX0_N
differential pair HDMI0_CLK: +HDMI0_CLK_P -HDMI0_CLK_N

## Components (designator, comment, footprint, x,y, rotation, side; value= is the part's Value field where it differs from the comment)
C1 "10uF_6.3V_0603" FP-C0603C106M9PACTU-MFG 601.3,1430 r270 bottom value=10uF
C2 "4.7uF_10V_0603" CAPC1608X87X35NL15T15 540,1425 r90 bottom
C3 "0.1uF_25V_0402" FP-0402-L_1_0_1-W_0_5_0_1-IPC_C 534.39,1510 r180 bottom
C4 "10uF_6.3V_0603" FP-C0603C106M9PACTU-MFG 515.48,1601.58 r180 bottom value=10uF
C5 "4.7uF_10V_0603" CAPC1608X87X35NL15T15 555,1660 r0 bottom
C6 "0.1uF_25V_0402" FP-0402-L_1_0_1-W_0_5_0_1-IPC_C 533,1552.79 r180 bottom
C7 "10uF_6.3V_0603" FP-C0603C106M9PACTU-MFG 735,1430 r270 bottom value=10uF
C8 "4.7uF_10V_0603" CAPC1608X87X35NL15T15 673.62,1427.48 r90 bottom
C9 "0.1uF_25V_0402" FP-0402-L_1_0_1-W_0_5_0_1-IPC_C 765,1515 r0 bottom
C10 "10uF_6.3V_0603" FP-C0603C106M9PACTU-MFG 715.23,1668.75 r0 bottom value=10uF
C11 "4.7uF_10V_0603" CAPC1608X87X35NL15T15 785,1610 r180 bottom
C12 "0.1uF_25V_0402" FP-0402-L_1_0_1-W_0_5_0_1-IPC_C 765,1555 r0 bottom
C13 "10uF_10V_0402" FP-CL05A106MP5NUNC-MFG 1135,1475 r270 top value=10uF
C14 "1uF_16V_0402" FP-0402-L_1_0_0_05-W_0_5-IPC_A 1198.84,1535 r0 top
C15 "10uf" FP-GRM188-0_2-IPC_C 4100,710 r180 top
C16 "0.1uF_16V_0402" FP-C0402-BB-MFG 1150,1595.75 r90 top value="0.10 μF"
C17 "10uF_10V_0402" FP-CL05A106MP5NUNC-MFG 1025,1540 r180 top value=10uF
C18 "1uF_16V_0402" FP-0402-L_1_0_0_05-W_0_5-IPC_A 1040,1470 r270 top
C19 "0.1uF_16V_0402" FP-C0402-BB-MFG 1090,1480 r270 top value="0.10 μF"
C20 "10uF_10V_0402" FP-CL05A106MP5NUNC-MFG 2773.21,1725 r180 top value=10uF
C21 "1uF_16V_0402" FP-0402-L_1_0_0_05-W_0_5-IPC_A 2865,1720 r0 top
C22 "0.1uF_16V_0402" FP-C0402-BB-MFG 2771.02,1680.79 r180 top value="0.10 μF"
C23 "10uF_10V_0402" FP-CL05A106MP5NUNC-MFG 2840.28,1567.16 r0 top value=10uF
C24 "1uF_16V_0402" FP-0402-L_1_0_0_05-W_0_5-IPC_A 2850,1615 r0 top
C25 "0.1uF_16V_0402" FP-C0402-BB-MFG 2784.81,1623.64 r90 top value="0.10 μF"
C26 "0.1uF_50V_0603" CAPC1608X90X35ML10T15 1580,700 r270 bottom
C27 "0.1uF_50V_0603" CAPC1608X90X35ML10T15 2460,695 r270 bottom
C28 "0.1uF_50V_0603" CAPC1608X90X35ML10T15 3476.88,875.34 r270 bottom
C29 "0.1uF_50V_0603" CAPC1608X90X35ML10T15 2380,815 r180 bottom
C30 "0.1uF_16V_0402" FP-GRM15-MFG 317.76,2033.62 r90 bottom value=0.10μF
C31 "0.1uF_50V_0603" CAPC1608X90X35ML10T15 1500,820 r180 bottom
C32 "0.1uF_25V_0402" FP-0402-L_1_0_1-W_0_5_0_1-IPC_C 2785,2295 r180 top
C33 "100nF" FP-GRM15-MFG 2750.75,3230 r180 top value=0.10μF
C34 "100nF" FP-GRM15-MFG 2740,3025 r180 top value=0.10μF
C35 "100uF_10V_1206" FP-C3216-160-0_3-IPC_C 175,3305 r180 top
C36 "10uF_10V_0402" FP-CL05A106MP5NUNC-MFG 115,2735 r180 top value=10uF
C37 "0.1uF_16V_0402" FP-C0402-BB-MFG 120,2860 r180 bottom value="0.10 μF"
C38 "4.7uF_10V_0402" FP-C1005-050-0_15-MFG 125,2810 r180 bottom
C39 "4.7uF_10V_0402" FP-C1005-050-0_15-MFG 125,2765 r180 bottom
C40 "22uF_10V_0603" CAPC1608X100X20ML10 295,3165.67 r90 top
C41 "22uF_10V_0603" CAPC1608X100X20ML10 100,2800 r0 top
C42 "10uF_10V_0402" FP-CL05A106MP5NUNC-MFG 275,3194.13 r270 bottom value=10uF
C43 "4.7uF_10V_0402" FP-C1005-050-0_15-MFG 335,3184.13 r270 bottom
C44 "0.1uF_16V_0402" FP-C0402-BB-MFG 220,3325 r180 bottom value="0.10 μF"
C45 "1uF_10V_0402" FP-CL511-IPC_C 215,3285 r180 bottom
C46 "10uF_10V_0402" FP-CL05A106MP5NUNC-MFG 125,2440 r180 bottom value=10uF
C47 "10uF_10V_0402" FP-CL05A106MP5NUNC-MFG 125,2440 r180 top value=10uF
C48 "10uF_10V_0402" FP-CL05A106MP5NUNC-MFG 115,3035 r180 bottom value=10uF
C49 "10uF_10V_0402" FP-CL05A106MP5NUNC-MFG 115,2980 r180 bottom value=10uF
C50 "22uF_10V_0603" CAPC1608X100X20ML10 100,2510 r0 top
C51 "22uF_10V_0603" CAPC1608X100X20ML10 100,3000 r0 top
C52 "10uF_10V_0402" FP-CL05A106MP5NUNC-MFG 230,2410 r0 bottom value=10uF
C53 "1uF_16V_0402" FP-0402-L_1_0_0_05-W_0_5-IPC_A 130,2390 r180 bottom
C54 "0.1uF_16V_0402" FP-C0402-BB-MFG 135,2395 r180 top value="0.10 μF"
C55 "22uF_10V_0603" CAPC1608X100X20ML10 240,2410 r180 top
C56 "10uF_10V_0402" FP-CL05A106MP5NUNC-MFG 425,2340 r90 top value=10uF
C57 "1uF_16V_0402" FP-0402-L_1_0_0_05-W_0_5-IPC_A 405,2340 r90 bottom
C58 "0.1uF_16V_0402" FP-C0402-BB-MFG 345,2340 r90 bottom value="0.10 μF"
C59 "22uF_10V_0603" CAPC1608X100X20ML10 355,2355 r270 top
C60 "0.1uF_16V_0402" FP-C0402-BB-MFG 65,2325 r180 top value="0.10 μF"
C61 "1nF_2KV_1206" FP-CC1206-0_3-1_45-IPC_C 70,3520 r90 top
C62 "0.1uF_16V_0402" FP-C0402-BB-MFG 540,2685 r0 top value="0.10 μF"
C63 "10uF_6.3V_0603" FP-C0603C106M9PACTU-MFG 3640,1914.39 r90 top value=10uF
C64 "4.7uF_10V_0603" CAPC1608X87X35NL15T15 3580,1914.39 r270 top
C65 "0.1uF_25V_0402" FP-0402-L_1_0_1-W_0_5_0_1-IPC_C 3510,1949.39 r90 top
C66 "10uF_6.3V_0603" FP-C0603C106M9PACTU-MFG 3325,1909.39 r90 top value=10uF
C67 "4.7uF_10V_0603" CAPC1608X87X35NL15T15 3387.55,1911.56 r270 top
C68 "0.1uF_25V_0402" FP-0402-L_1_0_1-W_0_5_0_1-IPC_C 3455,1949.39 r90 top
C69 "0.1uF_25V_0402" FP-0402-L_1_0_1-W_0_5_0_1-IPC_C 2385,1640 r90 bottom
C70 "10uF_6.3V_0603" FP-C0603C106M9PACTU-MFG 4094.53,520 r90 top value=10uF
C71 "4.7uF_10V_0603" CAPC1608X87X35NL15T15 4034.53,520 r270 top
C72 "0.1uF_25V_0402" FP-0402-L_1_0_1-W_0_5_0_1-IPC_C 3969.53,570 r90 top
C73 "10uF_6.3V_0603" FP-C0603C106M9PACTU-MFG 3774.53,520 r90 top value=10uF
C74 "4.7uF_10V_0603" CAPC1608X87X35NL15T15 3834.53,520 r270 top
C75 "0.1uF_25V_0402" FP-0402-L_1_0_1-W_0_5_0_1-IPC_C 3899.53,570 r90 top
C76 "0.1uF_25V_0402" FP-0402-L_1_0_1-W_0_5_0_1-IPC_C 2405,1870 r270 bottom
C77 "0.1uF_25V_0402" FP-0402-L_1_0_1-W_0_5_0_1-IPC_C 2240,1685 r0 bottom
C78 "10uF_6.3V_0603" FP-C0603C106M9PACTU-MFG 2526.3,2400 r180 top value=10uF
C79 "4.7uF_10V_0603" CAPC1608X87X35NL15T15 2526.3,2340 r0 top
C80 "0.1uF_25V_0402" FP-0402-L_1_0_1-W_0_5_0_1-IPC_C 2481.3,2270 r180 top
C81 "10uF_6.3V_0603" FP-C0603C106M9PACTU-MFG 2526.3,2080 r180 top value=10uF
C82 "4.7uF_10V_0603" CAPC1608X87X35NL15T15 2526.3,2140 r0 top
C83 "0.1uF_25V_0402" FP-0402-L_1_0_1-W_0_5_0_1-IPC_C 2481.3,2210 r180 top
C84 "0.1uF_25V_0402" FP-0402-L_1_0_1-W_0_5_0_1-IPC_C 2185.43,1736.04 r180 bottom
C85 "0.1uF_25V_0402" FP-0402-L_1_0_1-W_0_5_0_1-IPC_C 2181.26,1814.88 r180 bottom
C86 "0.1uF_25V_0402" FP-0402-L_1_0_1-W_0_5_0_1-IPC_C 2295.64,1930.96 r90 bottom
C87 "0.1uF_25V_0402" FP-0402-L_1_0_1-W_0_5_0_1-IPC_C 2360,1870 r270 bottom
C88 "0.1uF_25V_0402" FP-0402-L_1_0_1-W_0_5_0_1-IPC_C 2490,1930 r0 bottom
C89 "0.1uF_25V_0402" FP-0402-L_1_0_1-W_0_5_0_1-IPC_C 2260,1630 r90 bottom
C90 "10uF_6.3V_0603" FP-C0603C106M9PACTU-MFG 2100.08,2395.61 r270 top value=10uF
C91 "4.7uF_10V_0603" CAPC1608X87X35NL15T15 2160.08,2395.61 r90 top
C92 "0.1uF_25V_0402" FP-0402-L_1_0_1-W_0_5_0_1-IPC_C 2230.08,2355.61 r270 top
C93 "10uF_6.3V_0603" FP-C0603C106M9PACTU-MFG 2410.08,2400.61 r270 top value=10uF
C94 "4.7uF_10V_0603" CAPC1608X87X35NL15T15 2350.08,2395.61 r90 top
C95 "0.1uF_25V_0402" FP-0402-L_1_0_1-W_0_5_0_1-IPC_C 2285.08,2355.61 r270 top
C96 "0.1uF_25V_0402" FP-0402-L_1_0_1-W_0_5_0_1-IPC_C 2560,1805 r0 bottom
C97 "0.1uF_25V_0402" FP-0402-L_1_0_1-W_0_5_0_1-IPC_C 2560,1705 r0 bottom
C98 "10uF_6.3V_0603" FP-C0603C106M9PACTU-MFG 4100,285 r270 top value=10uF
C99 "4.7uF_10V_0603" CAPC1608X87X35NL15T15 4030,285 r90 top
C100 "0.1uF_25V_0402" FP-0402-L_1_0_1-W_0_5_0_1-IPC_C 3965,245 r270 top
C101 "10uF_6.3V_0603" FP-C0603C106M9PACTU-MFG 3780,290 r270 top value=10uF
C102 "4.7uF_10V_0603" CAPC1608X87X35NL15T15 3845,290 r90 top
C103 "0.1uF_25V_0402" FP-0402-L_1_0_1-W_0_5_0_1-IPC_C 3905,245 r270 top
C104 "0.1uF_25V_0402" FP-0402-L_1_0_1-W_0_5_0_1-IPC_C 2555,1650 r0 bottom
C105 "0.1uF_25V_0402" FP-0402-L_1_0_1-W_0_5_0_1-IPC_C 2560,1870 r0 bottom
C106 "10uF_6.3V_0603" FP-C0603C106M9PACTU-MFG 636.81,2218.15 r0 top value=10uF
C107 "4.7uF_10V_0603" CAPC1608X87X35NL15T15 526.81,2213.15 r0 top
C108 "0.1uF_25V_0402" FP-0402-L_1_0_1-W_0_5_0_1-IPC_C 639.9,2275.13 r0 top
C109 "10uF_6.3V_0603" FP-C0603C106M9PACTU-MFG 521.81,2403.15 r180 top value=10uF
C110 "4.7uF_10V_0603" CAPC1608X87X35NL15T15 629.39,2407.46 r180 top
C111 "0.1uF_25V_0402" FP-0402-L_1_0_1-W_0_5_0_1-IPC_C 516.81,2338.15 r180 top
C112 "0.1uF_25V_0402" FP-0402-L_1_0_1-W_0_5_0_1-IPC_C 1900,2100 r90 bottom
C113 "0.1uF_25V_0402" FP-0402-L_1_0_1-W_0_5_0_1-IPC_C 1900,1895 r0 bottom
C114 "0.1uF_25V_0402" FP-0402-L_1_0_1-W_0_5_0_1-IPC_C 1560,1715 r270 bottom
C115 "0.1uF_25V_0402" FP-0402-L_1_0_1-W_0_5_0_1-IPC_C 1360,1725 r180 bottom
C116 "0.1uF_25V_0402" FP-0402-L_1_0_1-W_0_5_0_1-IPC_C 1130,1890 r270 bottom
C117 "0.1uF_25V_0402" FP-0402-L_1_0_1-W_0_5_0_1-IPC_C 1115.61,2015 r0 bottom
C118 "0.1uF_25V_0402" FP-0402-L_1_0_1-W_0_5_0_1-IPC_C 1127.53,2194.37 r90 bottom
C119 "10uF_6.3V_0603" FP-C0603C106M9PACTU-MFG 2405,2240 r270 top value=10uF
C120 "4.7uF_10V_0603" CAPC1608X87X35NL15T15 2345,2243.43 r90 top
C121 "0.1uF_25V_0402" FP-0402-L_1_0_1-W_0_5_0_1-IPC_C 2280,2200 r270 top
C122 "10uF_6.3V_0603" FP-C0603C106M9PACTU-MFG 2090,2240 r270 top value=10uF
C123 "4.7uF_10V_0603" CAPC1608X87X35NL15T15 2155,2240 r90 top
C124 "0.1uF_25V_0402" FP-0402-L_1_0_1-W_0_5_0_1-IPC_C 2225,2200 r270 top
C125 "0.1uF_25V_0402" FP-0402-L_1_0_1-W_0_5_0_1-IPC_C 1895,2030 r0 bottom
C126 "0.1uF_25V_0402" FP-0402-L_1_0_1-W_0_5_0_1-IPC_C 1869.78,1986.96 r0 bottom
C127 "0.1uF_25V_0402" FP-0402-L_1_0_1-W_0_5_0_1-IPC_C 1685,1735 r270 bottom
C128 "0.1uF_25V_0402" FP-0402-L_1_0_1-W_0_5_0_1-IPC_C 1515,1740 r270 bottom
C129 "0.1uF_25V_0402" FP-0402-L_1_0_1-W_0_5_0_1-IPC_C 1435,1735 r270 bottom
C130 "0.1uF_25V_0402" FP-0402-L_1_0_1-W_0_5_0_1-IPC_C 1275,1730 r0 bottom
C131 "0.1uF_25V_0402" FP-0402-L_1_0_1-W_0_5_0_1-IPC_C 1123.5,1950.75 r270 bottom
C132 "0.1uF_25V_0402" FP-0402-L_1_0_1-W_0_5_0_1-IPC_C 1062.25,2041.34 r180 bottom
C133 "0.1uF_25V_0402" FP-0402-L_1_0_1-W_0_5_0_1-IPC_C 1153.7,2131.1 r0 bottom
C134 "10uF_6.3V_0603" FP-C0603C106M9PACTU-MFG 2460.47,2570 r270 top value=10uF
C135 "4.7uF_10V_0603" CAPC1608X87X35NL15T15 2400.47,2570 r90 top
C136 "0.1uF_25V_0402" FP-0402-L_1_0_1-W_0_5_0_1-IPC_C 2330.47,2510 r270 top
C137 "10uF_6.3V_0603" FP-C0603C106M9PACTU-MFG 2140.47,2563.62 r270 top value=10uF
C138 "4.7uF_10V_0603" CAPC1608X87X35NL15T15 2200.47,2561.57 r90 top
C139 "0.1uF_25V_0402" FP-0402-L_1_0_1-W_0_5_0_1-IPC_C 2270.47,2510 r270 top
C140 "0.1uF_25V_0402" FP-0402-L_1_0_1-W_0_5_0_1-IPC_C 1730,2570 r0 bottom
C141 "0.1uF_25V_0402" FP-0402-L_1_0_1-W_0_5_0_1-IPC_C 1025,2285 r180 bottom
C142 "0.1uF_25V_0402" FP-0402-L_1_0_1-W_0_5_0_1-IPC_C 1370,2595 r90 bottom
C143 "0.1uF_25V_0402" FP-0402-L_1_0_1-W_0_5_0_1-IPC_C 1730,2495 r0 bottom
C144 "0.1uF_25V_0402" FP-0402-L_1_0_1-W_0_5_0_1-IPC_C 1814.1,2291.29 r90 bottom
C145 "0.1uF_25V_0402" FP-0402-L_1_0_1-W_0_5_0_1-IPC_C 1813.74,2117.29 r90 bottom
C146 "0.1uF_25V_0402" FP-0402-L_1_0_1-W_0_5_0_1-IPC_C 1602.01,1730.27 r270 bottom
C147 "0.1uF_25V_0402" FP-0402-L_1_0_1-W_0_5_0_1-IPC_C 1405,1720 r270 bottom
C148 "0.1uF_25V_0402" FP-0402-L_1_0_1-W_0_5_0_1-IPC_C 1047.51,2210.58 r90 bottom
C149 "10uF_6.3V_0603" FP-C0603C106M9PACTU-MFG 2078.38,2940 r270 top value=10uF
C150 "4.7uF_10V_0603" CAPC1608X87X35NL15T15 2018.38,2940 r90 top
C151 "0.1uF_25V_0402" FP-0402-L_1_0_1-W_0_5_0_1-IPC_C 1948.38,2900 r270 top
C152 "10uF_6.3V_0603" FP-C0603C106M9PACTU-MFG 1768.38,2945 r270 top value=10uF
C153 "4.7uF_10V_0603" CAPC1608X87X35NL15T15 1828.38,2945 r90 top
C154 "0.1uF_25V_0402" FP-0402-L_1_0_1-W_0_5_0_1-IPC_C 1893.38,2900 r270 top
C155 "0.1uF_25V_0402" FP-0402-L_1_0_1-W_0_5_0_1-IPC_C 1585,2500 r180 bottom
C156 "0.1uF_25V_0402" FP-0402-L_1_0_1-W_0_5_0_1-IPC_C 1458.39,2581.29 r0 bottom
C157 "10uF_6.3V_0603" FP-C0603C106M9PACTU-MFG 2355,2815 r90 top value=10uF
C158 "4.7uF_10V_0603" CAPC1608X87X35NL15T15 2295,2815 r270 top
C159 "0.1uF_25V_0402" FP-0402-L_1_0_1-W_0_5_0_1-IPC_C 2230,2865 r90 top
C160 "10uF_6.3V_0603" FP-C0603C106M9PACTU-MFG 2045,2815 r90 top value=10uF
C161 "4.7uF_10V_0603" CAPC1608X87X35NL15T15 2105,2815 r270 top
C162 "0.1uF_25V_0402" FP-0402-L_1_0_1-W_0_5_0_1-IPC_C 2170,2865 r90 top
C163 "0.1uF_25V_0402" FP-0402-L_1_0_1-W_0_5_0_1-IPC_C 1454.06,2494.44 r0 bottom
C164 "0.1uF_25V_0402" FP-0402-L_1_0_1-W_0_5_0_1-IPC_C 1635,2580 r0 bottom
C165 "10uF_6.3V_0603" FP-C0603C106M9PACTU-MFG 1619.37,3121.95 r0 top value=10uF
C166 "4.7uF_10V_0603" CAPC1608X87X35NL15T15 1494.37,3061.95 r0 top
C167 "0.1uF_25V_0402" FP-0402-L_1_0_1-W_0_5_0_1-IPC_C 1664.69,3052.43 r0 top
C168 "10uF_6.3V_0603" FP-C0603C106M9PACTU-MFG 1614.37,2926.95 r0 top value=10uF
C169 "4.7uF_10V_0603" CAPC1608X87X35NL15T15 1489.37,2991.95 r0 top
C170 "0.1uF_25V_0402" FP-0402-L_1_0_1-W_0_5_0_1-IPC_C 1664.69,2997.43 r0 top
C171 "0.1uF_25V_0402" FP-0402-L_1_0_1-W_0_5_0_1-IPC_C 1920,2340 r0 bottom
C172 "0.1uF_25V_0402" FP-0402-L_1_0_1-W_0_5_0_1-IPC_C 1035,2375 r90 bottom
C173 "0.1uF_25V_0402" FP-0402-L_1_0_1-W_0_5_0_1-IPC_C 1665,2495 r180 bottom
C174 "0.1uF_16V_0402" FP-C0402-BB-MFG 1044.92,1877.29 r90 top value="0.10 μF"
C175 "0.1uF_16V_0402" FP-C0402-BB-MFG 2450,1545 r180 top value="0.10 μF"
C176 "22uF_10V_0603" CAPC1608X100X20ML10 1890,1820 r90 top
C177 "22uF_10V_0603" CAPC1608X100X20ML10 955,2005 r0 top
C178 "22uF_10V_0603" CAPC1608X100X20ML10 1855,2565 r180 top
C179 "22uF_10V_0603" CAPC1608X100X20ML10 1580,2663.46 r270 top
C180 "22uF_10V_0603" CAPC1608X100X20ML10 1675,2665 r270 top
C181 "22uF_10V_0603" CAPC1608X100X20ML10 1965,2340 r180 top
C182 "0.1uF_25V_0402" FP-0402-L_1_0_1-W_0_5_0_1-IPC_C 2315,1645 r90 bottom
C184 "0.1uF_25V_0402" FP-0402-L_1_0_1-W_0_5_0_1-IPC_C 2785,2330 r180 top
C186 "20pF_50V_0402" FP-C0402-BB-MFG 1150.57,2691.95 r0 top value="20 pF"
C187 "20pF_50V_0402" FP-C0402-BB-MFG 1200,2865 r270 top value="20 pF"
C188 "0.1uF_16V_0402" FP-GRM15-MFG 87.42,1378.14 r0 top value=0.10μF
C189 "0.1uF_50V_0603" FP-C0603-CJ-MFG 1325,3030 r180 bottom value=100nF
C190 "0.1uF_16V_0402" FP-GRM15-MFG 756.06,2561.57 r180 bottom value=0.10μF
C191 "0.1uF_16V_0402" FP-GRM15-MFG 1015,2875 r270 bottom value=0.10μF
C192 "0.1uF_16V_0402" FP-GRM15-MFG 1005.8,2777.63 r0 bottom value=0.10μF
C193 "0.1uF_16V_0402" FP-GRM15-MFG 1103.31,2727.56 r180 bottom value=0.10μF
C194 "0.1uF_16V_0402" FP-GRM15-MFG 1090,2830 r180 bottom value=0.10μF
C195 "0.1uF_16V_0402" FP-GRM15-MFG 877.18,2794.9 r90 bottom value=0.10μF
C196 "0.1uF_16V_0402" FP-GRM15-MFG 595.63,2678.82 r0 bottom value=0.10μF
C197 "0.1uF_16V_0402" FP-GRM15-MFG 615,2765 r0 bottom value=0.10μF
C198 "0.1uF_16V_0402" FP-GRM15-MFG 755,2525 r180 bottom value=0.10μF
C199 "0.1uF_16V_0402" FP-GRM15-MFG 609.82,2828.31 r0 bottom value=0.10μF
C200 "0.1uF_16V_0402" FP-GRM15-MFG 1015.82,2634.22 r0 bottom value=0.10μF
C201 "0.1uF_16V_0402" FP-GRM15-MFG 635,2570 r90 bottom value=0.10μF
C202 "0.1uF_16V_0402" FP-GRM15-MFG 1013.94,2742.68 r0 bottom value=0.10μF
C203 "0.1uF_16V_0402" FP-GRM15-MFG 1012.35,2701.42 r0 bottom value=0.10μF
C204 "0.1uF_16V_0402" FP-GRM15-MFG 1005,2810 r0 bottom value=0.10μF
C205 "0.1uF_16V_0402" FP-GRM15-MFG 1085,2865 r180 bottom value=0.10μF
C206 "0.1uF_16V_0402" FP-GRM15-MFG 924.37,2794.84 r90 bottom value=0.10μF
C207 "GRM188R61A226ME15D" FP-GRM188-0_2-IPC_C 1108.62,2868.31 r0 top
C208 "0.1uF_16V_0402" FP-GRM15-MFG 833.17,2789.12 r90 bottom value=0.10μF
C209 "GRM188R61A226ME15D" FP-GRM188-0_2-IPC_C 620.27,2724.51 r180 bottom
C210 "GRM188R61A226ME15D" FP-GRM188-0_2-IPC_C 972.99,2875.13 r90 bottom
C211 "GRM188R61A226ME15D" FP-GRM188-0_2-IPC_C 897.63,2896.83 r90 bottom
C212 "GRM188R61A226ME15D" FP-GRM188-0_2-IPC_C 587.52,2614.21 r270 bottom
C213 "GRM188R61A226ME15D" FP-GRM188-0_2-IPC_C 842.4,2894.69 r90 bottom
D1 "LTST-C190GKT" FP-LTST-C190GKT-MFG 4143.78,94.37 r0 top
D2 "LTST-C190GKT" FP-LTST-C190GKT-MFG 3983.78,94.37 r180 top
D3 "ESD122DMXR" FP-DMX0003A-MFG 1859.04,3066.95 r0 top
D4 "TVS0500DRVR" FP-DRV0006A-MFG 365,3295 r180 top
D5 "LTST-C190GKT" FP-LTST-C190GKT-MFG 465,3040 r90 top
D6 "LTST-C190GKT" FP-LTST-C190GKT-MFG 135,2610 r270 top
FB1 "BLM18KG221SN1D" FP-BLM18-0_15-t0_8-IPC_B 601.3,1545 r90 bottom
FB2 "BLM18KG221SN1D" FP-BLM18-0_15-t0_8-IPC_B 696.3,1545 r90 bottom
FB3 "MPZ2012S601A" TDK-MPZ2012_V 3670,175 r180 bottom
FB4 "MPZ2012S601A" TDK-MPZ2012_V 1400,3515 r180 bottom
FB5 "BLM18KG221SN1D" FP-BLM18-0_15-t0_8-IPC_B 3485,1879.39 r180 top
FB6 "BLM18KG221SN1D" FP-BLM18-0_15-t0_8-IPC_B 2255.08,2420.61 r0 top
FB7 "BLM18KG221SN1D" FP-BLM18-0_15-t0_8-IPC_B 3935,315 r180 top
FB8 "BLM18KG221SN1D" FP-BLM18-0_15-t0_8-IPC_B 581.09,2310.14 r90 top
FB9 "BLM18KG221SN1D" FP-BLM18-0_15-t0_8-IPC_B 2250,2265 r180 top
FB10 "BLM18KG221SN1D" FP-BLM18-0_15-t0_8-IPC_B 1923.38,2965 r180 top
FB11 "BLM18KG221SN1D" FP-BLM18-0_15-t0_8-IPC_B 2200,2795 r180 top
J1 "0845-2R1T-E4" FP-0845-2R1T-E4-MFG 1460,526 r0 top locked
J2 "0845-2R1T-E4" FP-0845-2R1T-E4-MFG 2339,526 r0 top locked
J3 "L829-1J1T-JM" BEL_L829-1J1T-JM 3225,410 r180 top locked
J4 "1367073-1" TECO-1367073-1_V 641.98,1493.47 r0 top locked
J5 "74754-0101" MOLX-74754-0101_V 641.98,1042.69 r180 top locked
J6 "U.FL-R-SMT-1(10)" FP-U_FL-R-SMT-1_10-MFG 215,1775 r90 top
J7 "685119134923" 685119134923 -47540.31,-46425.36 r180 top locked
J8 "61400416021" 61400416021 1755,3550 r180 top locked
J9 "12401610E4#2A" FP-12401610E4#2A-MFG 321.26,3595.91 r180 top locked
J10 "U.FL-R-SMT-1(10)" FP-U_FL-R-SMT-1_10-MFG 210,1565 r90 top
J11 "U.FL-R-SMT-1(10)" FP-U_FL-R-SMT-1_10-MFG 210,1360 r90 top
J12 "U.FL-R-SMT-1(10)" FP-U_FL-R-SMT-1_10-MFG 3270,3695 r180 top
J13 "U.FL-R-SMT-1(10)" FP-U_FL-R-SMT-1_10-MFG 3640,3705.04 r180 top
J14 "DF40HC(3.0)-100DS-0.4V(51" FP-DF40HC_3_0_-100DS-0_4V-MFG 2981.83,2586.75 r90 top locked
J15 "DF40HC(3.0)-100DS-0.4V(51" FP-DF40HC_3_0_-100DS-0_4V-MFG 4317.27,2586.75 r90 top locked
J16 "U.FL-R-SMT-1(10)" FP-U_FL-R-SMT-1_10-MFG 215,1985 r90 top
J17 "L829-1J1T-JM" BEL_L829-1J1T-JM 980,3390 r0 top locked
J18 "M20-9990246" FP-M20-9990246-MFG 4045,3690 r180 top
L1 "742692002" "WE-TMSB 0201" 1110,1540 r180 top
L2 "742692002" "WE-TMSB 0201" 2828.51,1667.34 r270 top
L3 "DLW21SN900HQ2L" FP-DLW21S-MFG 1943.46,3065.75 r0 top
L4 "DLM0QSN900HY2D" FP-DLM0Q-MFG 2264.88,3175.16 r270 top
L5 "DLM0QSN900HY2D" FP-DLM0Q-MFG 2344.45,3174.84 r270 top
L6 "DLM0QSN900HY2D" FP-DLM0Q-MFG 2420.55,3175.16 r270 top
L7 "DLM0QSN900HY2D" FP-DLM0Q-MFG 2494.45,3174.84 r270 top
L8 "DFE252012PD-R47M=P2" FP-DFE252012C-IPC_A 240,2950 r90 top
L9 "DFE252012PD-R47M=P2" FP-DFE252012C-IPC_A 240,2555 r270 top
L10 "1uH_4.1A_43mOhm" FP-CIGT201610-MFG 635,2730 r90 top
Q1 "BSS138-7-F" FP-SOT23_Standard-MFG 465,2840 r90 top
R1 "DNI_4.7K_1%_0402" RESC1005X40X25NL10T10 555,1201.73 r90 bottom
R2 "4.7K_1%_0402" RESC1005X40X25NL10T10 515,1200 r90 bottom
R3 "4.7K_1%_0402" RESC1005X40X25NL10T10 595,1200 r90 bottom
R4 "4.7K_1%_0402" RESC1005X40X25NL10T10 635,1205 r90 bottom
R5 "4.7K_1%_0402" RESC1005X40X25NL10T10 675.15,1205.88 r90 bottom
R6 "4.7K_1%_0402" RESC1005X40X25NL10T10 715,1205 r90 bottom
R7 "4.7K_1%_0402" RESC1005X40X25NL10T10 755,1205 r90 bottom
R8 "4.7K_1%_0402" RESC1005X40X25NL10T10 580,1315 r90 bottom
R9 "4.7K_1%_0402" RESC1005X40X25NL10T10 3095,2160 r180 bottom
R10 "10K_1%_0402" RESC1005X40X25NL10T10 2285,2120 r270 top
R11 "10K_1%_0402" RESC1005X40X25NL10T10 2330,2120 r270 top
R12 "10K_1%_0402" RESC1005X40X25NL10T10 2375,2120 r270 top
R13 "10K_1%_0402" RESC1005X40X25NL10T10 2420,2120 r270 top
R14 "22_1%_0402" RESC1005X40X25ML05T10 2235,2005 r270 top
R15 "22_1%_0402" RESC1005X40X25ML05T10 2105,1905 r0 top
R16 "22_1%_0402" RESC1005X40X25ML05T10 2420,2005 r270 top
R17 "22_1%_0402" RESC1005X40X25ML05T10 2375,2005 r270 top
R18 "22_1%_0402" RESC1005X40X25ML05T10 2330,2005 r270 top
R19 "22_1%_0402" RESC1005X40X25ML05T10 2285,2005 r270 top
R20 "22_1%_0402" RESC1005X40X25ML05T10 2105,1555 r0 top
R21 "22_1%_0402" RESC1005X40X25ML05T10 2105,1600 r0 top
R22 "22_1%_0402" RESC1005X40X25ML05T10 2105,1665 r0 top
R23 "22_1%_0402" RESC1005X40X25ML05T10 2105,1710 r0 top
R24 "22_1%_0402" RESC1005X40X25ML05T10 2105,1780 r0 top
R25 "22_1%_0402" RESC1005X40X25ML05T10 2105,1825 r0 top
R26 "330_1%_0402" RESC1005X40X25NL10T10 4114.59,169.34 r270 top
R27 "330_1%_0402" RESC1005X40X25NL10T10 3985,155 r270 top
R28 "10K_5%_0402" RESC1005X40X25ML05T05 4310,495 r0 top
R29 "0_5%_0402" RESC1005X40X25NL05T10 1045,1725 r90 top
R30 "0_5%_0402" RESC1005X40X25NL05T10 2600,1550 r180 top
R31 "220_1%_0402" RESC1005X40X25NL05T10 1100,205 r0 bottom
R32 "220_1%_0402" RESC1005X40X25NL05T10 1790,195 r180 bottom
R33 "220_1%_0402" RESC1005X40X25NL05T10 2050.16,1411.16 r270 top
R34 "220_1%_0402" RESC1005X40X25NL05T10 2615,1410 r270 bottom
R35 "220_1%_0402" RESC1005X40X25NL05T10 1970,405 r270 bottom
R36 "220_1%_0402" RESC1005X40X25NL05T10 2670,195 r180 bottom
R37 "220_1%_0402" RESC1005X40X25NL05T10 2945,1410 r270 bottom
R38 "220_1%_0402" RESC1005X40X25NL05T10 3110,115 r270 bottom
R39 "220_1%_0402" RESC1005X40X25NL05T10 1235,1395 r270 bottom
R40 "220_1%_0402" RESC1005X40X25NL05T10 1650.47,1370.79 r270 bottom
R41 "10K_1%_0402" RESC1005X40X25NL10T10 4390,2525 r0 bottom
R42 "191_1%_0402" RESC1005X40X25LL10T10 1555,2585 r0 bottom
R43 "0_5%_0402" RESC1005X40X25NL05T10 600,2520 r90 top
R44 "0_5%_0402" RESC1005X40X25NL05T10 4388.28,2464.7 r180 bottom
R45 "0_5%_0402" RESC1005X40X25NL05T10 4080,2445 r180 bottom
R46 "0_5%_0402" RESC1005X40X25NL05T10 4055,2550 r180 bottom
R47 "0_5%_0402" RESC1005X40X25NL05T10 4110,2495 r180 bottom
R48 "0_5%_0402" RESC1005X40X25NL05T10 90,1275 r270 top
R49 "0_5%_0402" RESC1005X40X25NL05T10 95,1590 r270 top
R50 "10K_1%_0402" RESC1005X40X25NL10T10 1705,2610 r0 bottom
R51 "6.04K_1%_0402" RESC1005X40X25NL10T10 1150,1726.73 r270 bottom
R52 "10K_1%_0402" RESC1005X40X25NL10T10 3020,2210 r0 bottom
R53 "220_1%_0402" RESC1005X40X25LL10T10 3440,189.76 r270 bottom
R54 "220_1%_0402" RESC1005X40X25LL10T10 3055,75 r90 bottom
R55 "10K_1%_0402" RESC1005X40X25NL10T10 2625,3220 r0 top
R56 "10K_1%_0402" RESC1005X40X25NL10T10 255,2735 r90 bottom
R57 "10K_1%_0402" RESC1005X40X25NL10T10 355,2800 r180 bottom
R58 "10K_1%_0402" RESC1005X40X25NL10T10 340,2945 r90 top
R59 "10K_1%_0402" RESC1005X40X25NL10T10 380,2945 r270 top
R60 "10K_1%_0402" RESC1005X40X25NL10T10 385,2550 r90 top
R61 "45.3K_1%_0402" RESC0402(1005)_L 350,2550 r90 top value="45300.00 Ohm"
R62 "0_5%_0402" RESC1005X40X25NL05T10 355,2840 r0 top
R63 "0_5%_0402" RESC1005X40X25NL05T10 355,2800 r0 top
R64 "0_5%_0402" RESC1005X40X25NL05T10 110,2685 r0 top
R65 "5.1K_1%_0402" RESC1005X40X25NL05T10 345,3575 r90 bottom
R66 "5.1K_1%_0402" RESC1005X40X25NL05T10 300,3575 r90 bottom
R67 "DNI_0_5%_0402" RESC1005X40X25NL05T10 355,2840 r180 bottom
R68 "8.06K_1%_0402" RESC1005X40X25ML05T05 355,2690 r180 top
R69 "10K_1%_0402" RESC1005X40X25NL10T10 192.6,2184.96 r90 bottom
R70 "330_1%_0402" RESC1005X40X25NL10T10 465,2948.27 r90 top
R71 "10K_1%_0402" RESC1005X40X25NL10T10 270,2183.27 r90 bottom
R72 "10K_1%_0402" RESC1005X40X25NL10T10 270,2315 r270 bottom
R73 "4.7K_1%_0402" RESC1005X40X25NL10T10 230,2315 r90 bottom
R74 "10K_1%_0402" RESC1005X40X25NL10T10 555,2785 r270 top
R75 "0_5%_0402" RESC1005X40X25NL05T10 582.2,2575.09 r180 top
R76 "0_1%_0805" RESC2013X60X35NL10T20 500,3305 r270 top
R77 "330_1%_0402" RESC1005X40X25NL10T10 85,2625 r90 top
R78 "0_5%_0402" RESC1005X40X25NL05T10 544.21,2628.28 r270 top
R79 "0_5%_0402" RESC1005X40X25NL05T10 435,2725 r180 top
R80 "10K_1%_0402" RESC1005X40X25NL10T10 510,2725 r180 top
R81 "0_5%_0402" RESC1005X40X25NL05T10 505,2625 r90 top
R82 "DNI_10K_1%_0402" RESC1005X40X25NL10T10 465,2685 r180 top
R83 "22_1%_0402" RESC1005X40X25ML05T10 505,2545 r90 top
R84 "22_1%_0402" RESC1005X40X25ML05T10 4105,2640 r180 bottom
R85 "10K_1%_0402" RESC1005X40X25NL10T10 2295,1525 r270 top
R86 "22_1%_0402" RESC1005X40X25ML05T10 4100,2590 r180 bottom
R87 "22_1%_0402" RESC1005X40X25ML05T10 4387.76,2574.94 r180 bottom
R88 "1K_1%_0402" RESC1005X40X25ML05T10 2205,1540 r0 top
R89 "12.1K_1%_0402" RESC1005X40X25NL10T10 2430,1646.73 r270 bottom
R90 "10K_1%_0402" RESC1005X40X25NL10T10 2335,1525 r270 top
R91 "0_5%_0603" RESC1608X55X25ML10T15 3934.53,495 r180 top
R92 "0_5%_0603" RESC1608X55X25ML10T15 2556.3,2240 r270 top
R93 "0_5%_0603" RESC1608X55X25ML10T15 2300.47,2585 r180 top
R94 "0_5%_0603" RESC1608X55X25ML10T15 1589.69,3027.43 r270 top
R95 "220_1%_0402" RESC1005X40X25NL05T10 2354.7,1961.19 r180 bottom
R96 "220_1%_0402" RESC1005X40X25NL05T10 2500,1965 r0 bottom
R97 "10K_1%_0402" RESC1005X40X25NL10T10 1650,95 r180 bottom
R98 "10K_1%_0402" RESC1005X40X25NL10T10 2505,1225 r180 bottom
R99 "10K_1%_0402" RESC1005X40X25NL10T10 3440,106.73 r270 bottom
R100 "10K_1%_0402" RESC1005X40X25NL10T10 2170,1220 r0 bottom
R101 "10K_1%_0402" RESC1005X40X25NL10T10 3015,115 r90 bottom
R102 "10K_1%_0402" RESC1005X40X25NL10T10 2530,105 r180 bottom
R103 "10K_1%_0402" RESC1005X40X25NL10T10 1630,1240 r180 bottom
R104 "DNI_0_5%_0402" RESC1005X40X25NL05T10 1063.63,1783.55 r0 top
R105 "DNI_0_5%_0402" RESC1005X40X25NL05T10 1027.61,1821.69 r0 top
R106 "DNI_0_5%_0402" RESC1005X40X25NL05T10 2543.19,1568.88 r90 top
R107 "DNI_0_5%_0402" RESC1005X40X25NL05T10 2505,1525 r90 top
R108 "220_1%_0402" RESC1005X40X25LL10T10 3000,210 r270 bottom
R109 "499_1%_0402" RESC1005X40X25LL05T05 673.06,2682.76 r180 bottom
R110 "499_1%_0402" RESC1005X40X25LL05T05 689.53,2558.36 r270 bottom
R111 "10K_1%_0402" RESC1005X40X25NL10T10 4300,2470 r180 bottom
R112 "0_5%_0402" RESC1005X40X25LL10T10 720.02,2604.88 r180 bottom
R113 "0_5%_0402" RESC1005X40X25LL10T10 700.5,2639.09 r180 bottom
R115 "0_5%_0402" RESC1005X40X25LL10T10 2785,2385 r180 top
R116 "0_5%_0402" RESC1005X40X25LL10T10 2785,2420 r180 top
R117 "0_5%_0402" RESC1005X40X25LL10T10 2800.02,2211.21 r180 top
R118 "0_5%_0402" RESC1005X40X25LL10T10 2800,2245 r180 top
R119 "10K_1%_0402" RESC1005X40X25NL10T10 3195,2325 r90 bottom
R121 "0_5%_0402" RESC1005X40X25LL10T10 95,1785 r90 top
R122 "0_5%_0402" RESC1005X40X25LL10T10 637.18,2533.99 r270 top
R124 "0_5%_0402" RESC1005X40X25LL10T10 450,1913.38 r180 top
R125 "0_5%_0402" RESC1005X40X25LL10T10 325.62,1900.67 r180 top
R126 "0_5%_0402" RESC1005X40X25LL10T10 375,2175 r270 top
R129 "0_5%_0402" RESC1005X40X25LL10T10 340,2175 r270 top
R130 "CRCW040210K0JNED" FP-CRCW0402-e3-IPC_B 327.61,1868.01 r180 top
R131 "0_5%_0402" RESC1005X40X25LL10T10 650,2415 r0 bottom
R132 "0_5%_0402" RESC1005X40X25LL10T10 705,2355 r90 bottom
R133 "0_5%_0402" RESC1005X40X25LL10T10 95,1995 r90 top
R134 "22K_1%_0402" RESC1005X40X25NL05T05 1105,2795 r180 bottom
R135 "200_1%_0402" FP-CRCW0402-e3-IPC_C 770,2350 r90 bottom
R136 "CRCW040210K0JNED" FP-CRCW0402-e3-IPC_B 205,1790 r90 bottom
R137 "CRCW040210K0JNED" FP-CRCW0402-e3-IPC_B 155,1290 r270 bottom
R138 "0_5%_0402" RESC1005X40X25LL10T10 1150,2775 r180 top
R139 "CRCW040210K0JNED" FP-CRCW0402-e3-IPC_B 450,1920 r270 bottom
R140 "0_5%_0402" RESC1005X40X25LL10T10 1150,2735 r180 top
R141 "CRCW040210K0JNED" FP-CRCW0402-e3-IPC_B 733.69,2715.12 r90 bottom
R142 "CRCW040210K0JNED" FP-CRCW0402-e3-IPC_B 651.37,2881.37 r90 bottom
R143 "CRCW040210K0JNED" FP-CRCW0402-e3-IPC_B 635,2505 r90 bottom
R144 "CRCW040210K0JNED" FP-CRCW0402-e3-IPC_B 712.21,2887.23 r90 bottom
R145 "CRCW040210K0JNED" FP-CRCW0402-e3-IPC_B 687.28,2791.12 r270 bottom
R146 "220_1%_0402" RESC1005X40X25LL10T10 790,3635 r0 bottom
R147 "DNI_10K" FP-CRCW0402-e3-IPC_B 751.48,2798.11 r180 bottom
R148 "CRCW040210K0JNED" FP-CRCW0402-e3-IPC_B 776.05,2456.04 r180 bottom
R149 "CRCW040210K0JNED" FP-CRCW0402-e3-IPC_B 1010.82,2589.31 r270 bottom
R150 "220_1%_0402" RESC1005X40X25LL10T10 1175,3740 r180 bottom
R151 "220_1%_0402" RESC1005X40X25LL10T10 1185,3540 r180 bottom
SD1 "503398-1892" MOLX-503398-1892_V 3975,1050 r270 top locked
U1 "KSZ9567STXI" FP-C04-418-IPC_A 1475,2155 r90 top locked
U2 "TPD4E05U06QDQARQ1" FP-DQA0010A-MFG 3890,2165 r0 top value=0.5pF
U3 "RT9742GGJ5" FP-RT9742GGJ5-IPC_C 4245,665 r0 top
U4 "KSZ9031RNXCC" MICL-QFN-48_V 2355,1755 r180 top locked
U5 "TPD4E05U06QDQARQ1" FP-DQA0010A-MFG 4310,2045 r90 top value=0.5pF
U6 "RT9742GGJ5" FP-RT9742GGJ5-IPC_C 2685,3125 r270 top
U7 "TPS62442QWRPSRQ1" FP-RQR0014A-MFG 248.63,2756.32 r180 top
U8 "LD39100PUR" DFN6D_M 230,2245 r90 top
U9 "SN74AUP1G08QDCKRQ1" DCK0005A_L 105,2230 r90 top
U10 "TPD4E05U06QDQARQ1" FP-DQA0010A-MFG 1340,1420 r90 top locked value=0.5pF
U11 "TPD4E05U06QDQARQ1" FP-DQA0010A-MFG 1785,1450 r90 top locked value=0.5pF
U12 "TPD4E05U06QDQARQ1" FP-DQA0010A-MFG 1605,1420 r90 top locked value=0.5pF
U13 "TPD4E05U06QDQARQ1" FP-DQA0010A-MFG 1921.84,1449.56 r90 top value=0.5pF
U14 "TPD4E05U06QDQARQ1" FP-DQA0010A-MFG 3225,1805 r180 bottom value=0.5pF
U15 "TPD4E05U06QDQARQ1" FP-DQA0010A-MFG 2150,1405 r270 bottom locked value=0.5pF
U16 "TPD4E05U06QDQARQ1" FP-DQA0010A-MFG 2804.69,1423.56 r270 top value=0.5pF
U17 "TPD4E05U06QDQARQ1" FP-DQA0010A-MFG 2435,1410 r90 top value=0.5pF
U18 "I225" "I225 QFN56" 885,2660 r0 top
U19 "TPD4E05U06QDQARQ1" FP-DQA0010A-MFG 1466.44,326.38 r0 bottom value=0.5pF
U20 "TMUX1574RSVR" FP-RSV0016A-MFG 365,2010 r90 top
U21 "TPD4E05U06QDQARQ1" FP-DQA0010A-MFG 1343.62,737.28 r90 bottom value=0.5pF
U22 "SST25VF016B-50-4C-S2AF" MCHP-SOIC-S2A8_M 180,1550 r270 bottom
U23 "TPD4EUSB30DQAR" DQA0010A_V 935,2900 r90 top
U24 "TPD4EUSB30DQAR" DQA0010A_V 805,2900 r90 top
Y1 "ECS-TXO-2520-33-250-AN-TR" FP-ECS-TXO-2520-MFG 1075,1625 r90 top
Y2 "ECS-TXO-2520-33-250-AN-TR" FP-ECS-TXO-2520-MFG 2700,1580 r180 top
Y3 "ABM8G-25.000MHZ-18-D2Y-T" FP-ABM8G-MFG 1289.14,2802.42 r270 top

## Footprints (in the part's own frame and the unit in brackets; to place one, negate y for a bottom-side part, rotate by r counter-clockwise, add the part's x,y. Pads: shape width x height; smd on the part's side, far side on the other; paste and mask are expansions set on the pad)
61400416021 [mm] "USB 2.0 Type A Horizontal"
  rrect50% 1.42x1.42 hole 0.92: 1(-3.5,5.99)
  round 1.42 hole 0.92: 2(-1,5.99) 3(1,5.99) 4(3.5,5.99)
  round 3.45 hole 2.3: Shell(-6.57,3.28) Shell(6.57,3.28)
  silkscreen extent -7.25,-7 7.25,7, body extent -8,-7 8,7, height 7.63
685119134923 [mm] "HDMI SMT Horizontal"
  rect 0.28x2.6 smd: 1(-1265.5,-1264.675) 2(-1266,-1264.675) 3(-1266.5,-1264.675) 4(-1267,-1264.675) 5(-1267.5,-1264.675) 6(-1268,-1264.675) 7(-1268.5,-1264.675) 8(-1269,-1264.675) 9(-1269.5,-1264.675) 10(-1270,-1264.675) 11(-1270.5,-1264.675) 12(-1271,-1264.675) 13(-1271.5,-1264.675) 14(-1272,-1264.675) 15(-1272.5,-1264.675) 16(-1273,-1264.675) 17(-1273.5,-1264.675) 18(-1274,-1264.675) 19(-1274.5,-1264.675)
  oval 1.5x2.7 hole 0.9 slot 2.1 at 90 deg: Shell(-1277.25,-1271.475) Shell(-1262.75,-1271.475)
  oval 1.5x3.3 hole 0.9 slot 2.7 at 90 deg: Shell(-1277.25,-1265.475) Shell(-1262.75,-1265.475)
  silkscreen extent -1277.5,-1274.78 -1262.5,-1263.93, body extent -1277.55,-1276.07 -1262.55,-1263.92, height 6.17
BEL_L829-1J1T-JM [mm]
  rect 1.53x1.53 hole 1.02: 1(-5.08,-6.604)
  round 1.53 hole 1.02: 2(-3.048,-6.604) 3(-1.016,-6.604) 4(1.016,-6.604) 5(3.048,-6.604) 6(5.08,-6.604) 7(-6.096,-9.144) 8(-4.064,-9.144) 9(-2.032,-9.144) 10(2.032,-9.144) 11(4.064,-9.144) 12(6.096,-9.144)
  round 1.905 hole 1.27: 13(-7.518,6.35) 14(-7.518,8.89) 15(7.518,3.81) 16(7.518,6.35) 17(7.518,8.89)
  round 2.355 hole 1.57: S1(-8.788,0) S2(8.788,0)
  round 3.25 hole 3.25 unplated: ""(-4.826,0) ""(4.826,0)
  silkscreen extent -9.6,-10.8 8.79,13.21
CAPC1608X87X35NL15T15 [mm] "Chip Capacitor, 2-Leads, Body 1.60x0.80mm, IPC Medium Density"
  rect 0.9x1 smd: 1(-0.675,0) 2(0.675,0)
  body extent -0.87,-0.48 0.87,0.47, height 0.87
CAPC1608X90X35ML10T15 [mm] "Chip Capacitor, 2-Leads, Body 1.7x0.9mm, IPC Low Density"
  rect 0.95x1.05 smd: 1(-0.725,0) 2(0.725,0)
  body extent -0.85,-0.45 0.85,0.45, height 0.9
CAPC1608X100X20ML10 [mm] "Chip Capacitor, 2-Leads, Body 1.70x0.90mm, IPC Low Density"
  rect 0.65x1.05 smd: 1(-0.85,0) 2(0.85,0)
  silkscreen extent -0.15,-0.43 0.15,0.43, body extent -0.85,-0.45 0.85,0.45, height 1
DCK0005A_L [mm] "SOT23, 5-Leads, Body 2.15x1.4mm, Pitch 0.65mm, IPC High Density"
  rrect25% 0.65x0.4 smd: 1(-1.025,0.65) 2(-1.025,0) 3(-1.025,-0.65) 4(1.025,-0.65) 5(1.025,0.65)
  silkscreen extent -1.15,-1.1 0.3,1.52, body extent -1.14,-1 1.14,1, height 0.94
DFN6D_M [mm] "SON, 6-Leads, Body 3x3mm, Pitch 0.95mm, Thermal Pad 2.4x1.65mm, IPC Low Density"
  oval 0.9x0.4 smd: 1(-1.525,0.95) 2(-1.525,0) 3(-1.525,-0.95) 4(1.525,-0.95) 5(1.525,0) 6(1.525,0.95)
  rect 1.65x2.4 smd: 7(0,0)
  silkscreen extent -2.15,-1.7 1.7,1.75, body extent -1.55,-1.55 1.55,1.55, height 0.95
DQA0010A_V [mm] "SON, 10-Leads, Body 1x2.5mm, Pitch 0.5mm, TI Recommended"
  rrect50% 0.565x0.2 smd: 1(-0.417,1) 2(-0.417,0.5) 4(-0.417,-0.5) 5(-0.417,-1) 6(0.417,-1) 7(0.417,-0.5) 9(0.417,0.5) 10(0.417,1)
  rrect28% 0.565x0.36 on Top Paste: 3(-0.417,0) 8(0.417,0)
  rrect25% 0.565x0.4 smd paste-0.2: 3(-0.417,0) 8(0.417,0)
  silkscreen extent -0.67,-1.45 0.55,1.45, body extent -0.55,-1.3 0.55,1.3, height 0.56
FP-0402-L_1_0_0_05-W_0_5-IPC_A [mil]
  rect 28.16x26.48 smd paste+0 mask+0: 1(-18.84,0) 2(18.84,0)
  silkscreen extent -33,-29 33,29, body extent -41,-21 41,21, height 10
FP-0402-L_1_0_1-W_0_5_0_1-IPC_C [mil]
  rect 22.88x20.16 smd paste+0 mask+0: 1(-14.39,0) 2(14.39,0)
  silkscreen extent -26,-28 26,28, body extent -20,-10 20,10, height 22
FP-0845-2R1T-E4-MFG [mil]
  rect 54.69x54.69 hole 35 paste-99999 mask+0: 1(-237,-36)
  round 54.69 hole 35 paste-99999 mask+0: 2(-158,-36) 3(-79,-36) 4(0,-36) 5(79,-36) 6(158,-36) 7(237,-36) 8(-197,64) 9(-118,64) 10(-39,64) 11(40,64) 12(119,64) 13(198,64) 14(-237,374) 15(-158,374) 16(-79,374) 17(0,374) 18(79,374) 19(158,374) 20(237,374) 21(-197,474) 22(-118,474) 23(-39,474) 24(40,474) 25(119,474) 26(198,474)
  round 61.65 hole 40 paste-99999 mask+0: 27(-234,-355) 28(-154,-355) 29(154,-355) 30(234,-355) 31(-215,624) 32(-115,624) 33(115,624) 34(215,624)
  round 95.46 hole 62 paste-99999 mask+0: 35(-330.5,221) 36(330.5,221) 37(-330.5,-423) 38(330.5,-423)
  round 128 hole 128 unplated paste-99999 mask+0: ""(-258,-243) ""(258,-243)
  silkscreen extent -443,-668 414,668, body extent -418,-671 418,671, height 10
FP-12401610E4#2A-MFG [mm]
  rrect100% 0.8x1.4 hole 1.1 slot 0.5 at 0 deg paste-2539.97 mask+0: 1(-4.13,3.115) 2(4.13,3.115) 3(-4.49,-2.835) 4(4.49,-2.835)
  rect 0.3x0.7 smd paste+0 mask+0: A1(-2.75,5.025) A2(-2.25,5.025) A3(-1.75,5.025) A4(-1.25,5.025) A5(-0.75,5.025) A6(-0.25,5.025) A7(0.25,5.025) A8(0.75,5.025) A9(1.25,5.025) A10(1.75,5.025) A11(2.25,5.025) A12(2.75,5.025) B1(2.5,3.325) B2(2,3.325) B3(1.5,3.325) B4(1,3.325) B5(0.5,3.325) B6(0,3.325) B7(-0.5,3.325) B8(-1,3.325) B9(-1.5,3.325) B10(-2,3.325) B11(-2.5,3.325) B12(-3,3.325)
  round 0.65 hole 0.65 unplated paste-2539.97 mask+0: ""(-3.6,4.365)
  rrect100% 0.95x0.65 hole 0.65 slot 0.95 at 0 deg unplated paste-2539.97 mask+0: ""(3.6,4.365)
  silkscreen extent -4.72,-1.76 4.72,6.09, body extent -4.99,-5.45 4.99,5.48, height 0.25
FP-ABM8G-MFG [mm]
  rect 1.4x1.2 smd paste+0 mask+0: 1(-1.1,-0.85) 2(1.1,-0.85) 3(1.1,0.85) 4(-1.1,0.85)
  silkscreen extent -2.47,-1.3 0.03,1.3, body extent -1.9,-1.55 1.9,1.55, height 0.25
FP-BLM18-0_15-t0_8-IPC_B [mil]
  rect 43.55x37.73 smd paste+0 mask+0: 1(-26.62,0) 2(26.62,0)
  silkscreen extent -48,-35 48,35, body extent -31,-16 31,16, height 37
FP-C04-418-IPC_A [mm]
  rect 1.955x0.272 smd paste+0 mask+0: 1(-7.675,6.2)
  rrect100% 1.955x0.272 smd paste+0 mask+0: 2(-7.675,5.8) 3(-7.675,5.4) 4(-7.675,5) 5(-7.675,4.6) 6(-7.675,4.2) 7(-7.675,3.8) 8(-7.675,3.4) 9(-7.675,3) 10(-7.675,2.6) 11(-7.675,2.2) 12(-7.675,1.8) 13(-7.675,1.4) 14(-7.675,1) 15(-7.675,0.6) 16(-7.675,0.2) 17(-7.675,-0.2) 18(-7.675,-0.6) 19(-7.675,-1) 20(-7.675,-1.4) 21(-7.675,-1.8) 22(-7.675,-2.2) 23(-7.675,-2.6) 24(-7.675,-3) 25(-7.675,-3.4) 26(-7.675,-3.8) 27(-7.675,-4.2) 28(-7.675,-4.6) 29(-7.675,-5) 30(-7.675,-5.4) 31(-7.675,-5.8) 32(-7.675,-6.2) 65(7.675,-6.2) 66(7.675,-5.8) 67(7.675,-5.4) 68(7.675,-5) 69(7.675,-4.6) 70(7.675,-4.2) 71(7.675,-3.8) 72(7.675,-3.4) 73(7.675,-3) 74(7.675,-2.6) 75(7.675,-2.2) 76(7.675,-1.8) 77(7.675,-1.4) 78(7.675,-1) 79(7.675,-0.6) 80(7.675,-0.2) 81(7.675,0.2) 82(7.675,0.6) 83(7.675,1) 84(7.675,1.4) 85(7.675,1.8) 86(7.675,2.2) 87(7.675,2.6) 88(7.675,3) 89(7.675,3.4) 90(7.675,3.8) 91(7.675,4.2) 92(7.675,4.6) 93(7.675,5) 94(7.675,5.4) 95(7.675,5.8) 96(7.675,6.2)
  rrect100% 0.272x1.955 smd paste+0 mask+0: 33(-6.2,-7.675) 34(-5.8,-7.675) 35(-5.4,-7.675) 36(-5,-7.675) 37(-4.6,-7.675) 38(-4.2,-7.675) 39(-3.8,-7.675) 40(-3.4,-7.675) 41(-3,-7.675) 42(-2.6,-7.675) 43(-2.2,-7.675) 44(-1.8,-7.675) 45(-1.4,-7.675) 46(-1,-7.675) 47(-0.6,-7.675) 48(-0.2,-7.675) 49(0.2,-7.675) 50(0.6,-7.675) 51(1,-7.675) 52(1.4,-7.675) 53(1.8,-7.675) 54(2.2,-7.675) 55(2.6,-7.675) 56(3,-7.675) 57(3.4,-7.675) 58(3.8,-7.675) 59(4.2,-7.675) 60(4.6,-7.675) 61(5,-7.675) 62(5.4,-7.675) 63(5.8,-7.675) 64(6.2,-7.675) 97(6.2,7.675) 98(5.8,7.675) 99(5.4,7.675) 100(5,7.675) 101(4.6,7.675) 102(4.2,7.675) 103(3.8,7.675) 104(3.4,7.675) 105(3,7.675) 106(2.6,7.675) 107(2.2,7.675) 108(1.8,7.675) 109(1.4,7.675) 110(1,7.675) 111(0.6,7.675) 112(0.2,7.675) 113(-0.2,7.675) 114(-0.6,7.675) 115(-1,7.675) 116(-1.4,7.675) 117(-1.8,7.675) 118(-2.2,7.675) 119(-2.6,7.675) 120(-3,7.675) 121(-3.4,7.675) 122(-3.8,7.675) 123(-4.2,7.675) 124(-4.6,7.675) 125(-5,7.675) 126(-5.4,7.675) 127(-5.8,7.675) 128(-6.2,7.675)
  rect 10.15x10.15 smd paste-1000 mask+0: 129(0,0)
  silkscreen extent -7.8,-7 7,7.09, body extent -9.15,-9.15 9.15,9.15, height 0.25
FP-C0402-BB-MFG [mm]
  rect 0.52x0.52 smd paste+0 mask+0: 1(-0.4,0) 2(0.4,0)
  silkscreen extent -0.5,-0.64 0.5,0.64, body extent -0.8,-0.4 0.8,0.4, height 0.25
FP-C0603-CJ-MFG [mm]
  rect 0.85x0.9 smd paste+0 mask+0: 1(-0.65,0) 2(0.65,0)
  silkscreen extent -0.8,-0.85 0.8,0.85, body extent -0.8,-0.4 0.8,0.4, height 0.95
FP-C0603C106M9PACTU-MFG [mm]
  rect 0.75x0.9 smd paste+0 mask+0: 1(-0.6,0) 2(0.6,0)
  silkscreen extent -0.88,-0.83 0.87,0.82, body extent -0.8,-0.4 0.8,0.4, height 0.9
FP-C1005-050-0_15-MFG [mm]
  rect 0.4x0.5 smd paste+0 mask+0: 1(-0.4,0) 2(0.4,0)
  silkscreen extent -0.5,-0.72 0.5,0.72, body extent -0.5,-0.25 0.5,0.25, height 0.55
FP-C3216-160-0_3-IPC_C [mil]
  rect 63.15x71.11 smd paste+0 mask+0: 1(-43.35,0) 2(43.35,0)
  silkscreen extent -75,-53 75,53, body extent -79,-41 79,41, height 10
FP-CC1206-0_3-1_45-IPC_C [mil]
  rect 47.38x67.17 smd paste+0 mask+0: 1(-51.2,0) 2(51.2,0)
  silkscreen extent -16,-35 16,35, body extent -79,-39 79,39, height 10
FP-CIGT201610-MFG [mm]
  rect 0.8x1.8 smd paste+0 mask+0: 1(-0.8,0) 2(0.8,0)
  silkscreen extent 0,-0.9 0,0.9, body extent -1.3,-1 1.3,1, height 0.25
FP-CL05A106MP5NUNC-MFG [mm]
  rect 0.45x0.675 smd paste+0 mask+0: 1(-0.463,0) 2(0.463,0)
  silkscreen extent -0.6,-0.63 0.6,0.63, body extent -0.79,-0.45 0.79,0.45, height 0.25
FP-CL511-IPC_C [mil]
  rect 20.29x18.6 smd paste+0 mask+0: 1(-14.9,0) 2(14.9,0)
  silkscreen extent -25,-27 25,27, body extent -20,-10 20,10, height 22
